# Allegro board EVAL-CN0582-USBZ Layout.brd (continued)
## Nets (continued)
UNNAMED_27_ADA45221_I223_: A14.2 R312.1 R318.2(N2)
UNNAMED_27_ADA45221_I223_OUT: A14.6 D4.3 R312.2(N2) R351.2(N2) TP59.1(N1)
UNNAMED_27_ADA45221_I227_: A5.3 C185.2(N2) R160.2(N2)
UNNAMED_27_ADG1219_I151_D: A14.3 TP57.1(N1) U32.6
UNNAMED_27_ADG1219_I151_EN: R310.2(N2) U32.1
UNNAMED_27_ADG1219_I151_SB: A5.6 C216.1 R112.1 TP32.1(N1) U32.5
UNNAMED_27_CAP_I189_N2: C243.2(N2) C244.1 R148.2(N2) R157.1 R311.1 R345.1
UNNAMED_27_CAP_I238_N2: C291.2(N2) R343.2(N2)
UNNAMED_27_CAP_I250_N2: C216.2(N2) R159.2(N2) R160.1
UNNAMED_27_CNBNC2P_I81_CNTR: D4.4 D5.2(N2) J6.1 R351.1
UNNAMED_27_DIO4PV11_I83_A1: D4.1 R121.2(N2)
UNNAMED_27_DIO4PV11_I83_K2: D4.2(K2) R228.2(N2)
UNNAMED_27_RES_I13_N2: R153.2(N2) Y4.3
UNNAMED_27_RES_I119_N2: A5.2 R99.2(N2) R112.2(N2)
UNNAMED_28_AD568XRV5_I11_VREF: C146.2(N2) R128.1 U16.15(VREF)
UNNAMED_28_AD77684_I28_AVDD1A: C163.1 C164.1 E2.2(N2) U18.4 U18.45
UNNAMED_28_AD77684_I28_AVDD2A: C165.1 C166.1 E3.2(N2) U18.53 U18.60
UNNAMED_28_AD77684_I28_DIN: R150.2(N2) U18.21
UNNAMED_28_AD77684_I28_DNC: R258.1 U18.20
UNNAMED_28_AD77684_I28_DREGCAP: C169.1 C171.1 U18.34
UNNAMED_28_AD77684_I28_IOVDD: C167.2(N2) C168.2(N2) E4.1 U18.35
UNNAMED_28_AD77684_I28_PINN: R149.2(N2) TP7.1(N1) U18.57
UNNAMED_28_AD77684_I28_REG1CAPA: C174.1 C175.1 U18.61
UNNAMED_28_AD77684_I28_REG2CAPB: C172.1 C173.1 U18.52
UNNAMED_28_AD77684_I28_SYNCOUTN: R151.2(N2) U18.38
UNNAMED_28_ADA48071_I285_: A6.4 C152.1 R139.1
UNNAMED_28_ADA48071_I285__1: A6.3 R132.2(N2)
UNNAMED_28_ADA48071_I292_: A9.4 R142.1 R143.2(N2)
UNNAMED_28_ADA48071_I307_: A15.4 C101.1 R195.2(N2)
UNNAMED_28_ADA48071_I307__1: A15.3 C99.1 R117.2(N2) R190.2(N2)
UNNAMED_28_ADA48071_I307_DISABLEN: A15.5 R319.1
UNNAMED_28_ADA48071_I307_VOUT: A15.1(VOUT) C101.2(N2) R195.1 R253.1
UNNAMED_28_CAP_I178_N1: C12.1 E16.2(N2) R6.1 Y3.4(VCC)
UNNAMED_28_CAP_I209_N1: C13.1 E17.2(N2) R77.1 Y5.4
UNNAMED_28_CAP_I254_N2: A6.1(VOUT) C152.2(N2) R138.1
UNNAMED_28_CAP_I282_N2: C154.2(N2) R131.2(N2) R135.1
UNNAMED_28_NCTESTPAD_I237_N1: R255.2(N2) R256.1 R257.1 TP18.1(N1)
UNNAMED_28_RES_I152_N2: A9.3 R135.2(N2) R254.1
UNNAMED_28_RES_I334_N1: R373.1 Y3.3
UNNAMED_28_RES_I335_N2: Q10.G R372.2(N2) R374.1
UNNAMED_28_RES_I336_N2: R77.2(N2) R374.2(N2) Y5.1
UNNAMED_28_RES_I338_N2: Q10.D R6.2(N2) Y3.1
UNNAMED_28_RES_I341_N1: R375.1 Y5.3(OUTPUT)
UNNAMED_29_ADP1708_I198_ADJ: R226.1 R227.1 U26.8
UNNAMED_29_ADP1708_I198_EN: R224.1 U26.1
UNNAMED_29_ADP1708_I198_IN: C208.2(N2) R224.2(N2) R274.1 R275.1 U26.3 U26.4
UNNAMED_29_ADP1708_I198_SENSE: R225.2(N2) U26.7(SENSE)
UNNAMED_29_CAP_I53_N1: C142.1 U1.A5
UNNAMED_29_CAP_I54_N1: C141.1 U1.A6
UNNAMED_29_CAP_I143_N1: C90.1 D6.C R231.2(N2) U1.E10
UNNAMED_29_CAP_I208_N2: C271.2(N2) U1.A4
UNNAMED_29_CAP_I209_N2: C272.2(N2) U1.A3
UNNAMED_29_DIOSCHOTTKY_I142_P: D6.A(P) P8.2 R231.1
UNNAMED_29_ICCYUSB301X_I1_CLKIN: TP1.1(N1) U1.D7
UNNAMED_29_ICCYUSB301X_I1_GPIO: R140.2(N2) U1.J6
UNNAMED_29_ICCYUSB301X_I1_GPIO_1: R133.2(N2) U1.K10
UNNAMED_29_ICCYUSB301X_I1_GPIO_2: R120.2(N2) U1.F7
UNNAMED_29_ICCYUSB301X_I1_GPIO_3: R268.2(N2) U1.G10
UNNAMED_29_ICCYUSB301X_I1_GPIO_4: R122.2(N2) U1.G9
UNNAMED_29_ICCYUSB301X_I1_GPIO_5: R124.2(N2) U1.H10
UNNAMED_29_ICCYUSB301X_I1_GPIO_6: R119.2(N2) U1.F9
UNNAMED_29_ICCYUSB301X_I1_GPIO_7: R136.2(N2) U1.J8
UNNAMED_29_ICCYUSB301X_I1_GPIO_8: R134.2(N2) U1.K9
UNNAMED_29_ICCYUSB301X_I1_GPIO_9: R137.2(N2) U1.G8
UNNAMED_29_ICCYUSB301X_I1_GPIO_10: R152.2(N2) U1.G6
UNNAMED_29_ICCYUSB301X_I1_GPIO_11: R144.2(N2) U1.K7
UNNAMED_29_ICCYUSB301X_I1_GPIO_12: R174.1 U1.D4
UNNAMED_29_ICCYUSB301X_I1_GPIO_13: R176.1 U1.C2
UNNAMED_29_ICCYUSB301X_I1_GPIO_14: R175.1 U1.C1
UNNAMED_29_ICCYUSB301X_I1_GPIO_15: R273.1 U1.D3
UNNAMED_29_ICCYUSB301X_I1_GPIO_16: R173.1 U1.D2
UNNAMED_29_ICCYUSB301X_I1_GPIO_17: R177.1 U1.D5
UNNAMED_29_ICCYUSB301X_I1_GPIO_18: R172.1 U1.D1
UNNAMED_29_ICCYUSB301X_I1_GPIO_19: R270.1 U1.C4
UNNAMED_29_ICCYUSB301X_I1_GPIO_20: R219.1 U1.E5
UNNAMED_29_ICCYUSB301X_I1_GPIO_21: R171.1 U1.E4
UNNAMED_29_ICCYUSB301X_I1_GPIO_22: R169.1 U1.H4
UNNAMED_29_ICCYUSB301X_I1_GPIO_23: R271.1 U1.H5
UNNAMED_29_ICCYUSB301X_I1_GPIO_24: R170.1 U1.L4
UNNAMED_29_ICCYUSB301X_I1_GPIO_25: R215.1 U1.F4
UNNAMED_29_ICCYUSB301X_I1_GPIO_26: R232.1 U1.F5
UNNAMED_29_ICCYUSB301X_I1_GPIO_27: R272.1 U1.F2
UNNAMED_29_ICCYUSB301X_I1_GPIO_28: R213.1 U1.H2
UNNAMED_29_ICCYUSB301X_I1_GPIO_29: R212.1 U1.J1
UNNAMED_29_ICCYUSB301X_I1_GPIO_30: R218.1 U1.F3
UNNAMED_29_ICCYUSB301X_I1_GPIO_31: R214.1 U1.H3
UNNAMED_29_ICCYUSB301X_I1_GPIO_32: R216.1 U1.G2
UNNAMED_29_ICCYUSB301X_I1_GPIO_33: R217.1 U1.G3
UNNAMED_29_ICCYUSB301X_I1_GPIO_34: R233.1 U1.E1
UNNAMED_29_ICCYUSB301X_I1_GPIO_35: R161.1 U1.J3
UNNAMED_29_ICCYUSB301X_I1_GPIO_36: R168.1 U1.G4
UNNAMED_29_ICCYUSB301X_I1_GPIO_37: R220.1 U1.K2
UNNAMED_29_ICCYUSB301X_I1_GPIO_38: R221.1 U1.J4
UNNAMED_29_ICCYUSB301X_I1_GPIO_39: R222.1 U1.K1
UNNAMED_29_ICCYUSB301X_I1_GPIO_40: R223.1 U1.J2
UNNAMED_29_ICCYUSB301X_I1_GPIO_41: R118.2(N2) U1.F10
UNNAMED_29_ICCYUSB301X_I1_GPIO_42: R130.2(N2) U1.L10
UNNAMED_29_ICCYUSB301X_I1_GPIO_43: R129.2(N2) U1.K11
UNNAMED_29_ICCYUSB301X_I1_GPIO_44: R127.2(N2) U1.J9
UNNAMED_29_ICCYUSB301X_I1_GPIO_45: R126.2(N2) U1.J10
UNNAMED_29_ICCYUSB301X_I1_GPIO_46: R125.2(N2) U1.H9
UNNAMED_29_ICCYUSB301X_I1_GPIO_47: R123.2(N2) U1.F8
UNNAMED_29_ICCYUSB301X_I1_GPIO_48: R165.2(N2) U1.K5
UNNAMED_29_ICCYUSB301X_I1_GPIO_49: R166.2(N2) U1.J5
UNNAMED_29_ICCYUSB301X_I1_GPIO_50: R164.2(N2) U1.H6
UNNAMED_29_ICCYUSB301X_I1_GPIO_51: R163.2(N2) U1.G5
UNNAMED_29_ICCYUSB301X_I1_GPIO_52: R162.2(N2) U1.H8
UNNAMED_29_ICCYUSB301X_I1_GPIO_53: R147.2(N2) U1.G7
UNNAMED_29_ICCYUSB301X_I1_GPIO_54: R146.2(N2) U1.H7
UNNAMED_29_ICCYUSB301X_I1_GPIO_55: R145.2(N2) U1.J7
UNNAMED_29_ICCYUSB301X_I1_GPIO_56: R141.2(N2) U1.K8
UNNAMED_29_ICCYUSB301X_I1_GPIO_57: R269.2(N2) U1.K6
UNNAMED_29_ICCYUSB301X_I1_I2CGPIO: R235.1 U1.D10
UNNAMED_29_ICCYUSB301X_I1_I2CGPIO_1: R234.1 U1.D9
UNNAMED_29_ICCYUSB301X_I1_O: TP3.1(N1) U1.D11
UNNAMED_29_ICCYUSB301X_I1_RUSB2: R178.2(N2) U1.C8
UNNAMED_29_ICCYUSB301X_I1_RUSB3: R167.2(N2) U1.B3
UNNAMED_30_CN10P_I90_N1: P7.1 R230.1
UNNAMED_30_DIOLED_I129_N: DS2.C R182.1
UNNAMED_30_RES_I2_N1: R183.1 Y2.3
UNNAMED_30_RES_I10_N2: R180.2(N2) Y2.1
UNNAMED_30_RES_I76_N1: R191.1 S1.1B(N4)
UNNAMED_30_RES_I130_N2: Q2.D R182.2(N2)
UNNAMED_30_RES_I131_N2: Q2.G R181.2(N2)
UNNAMED_31_74LVC1G04_I124_A: R334.1 U37.5 U38.2
UNNAMED_31_74LVC1G04_I124_Y: R335.1 R340.2(N2) U38.4(Y) U41.2
UNNAMED_31_74LVC1G04_I136_Y: R339.2(N2) U41.4(Y)
UNNAMED_31_ADG839_I121_S1: D19.2(N2) P5.2 R337.1 R338.2(N2) U37.4
UNNAMED_31_ADLTC4332_I1_LINKN: R249.2(N2) U12.5
UNNAMED_31_ADLTC4332_I1_REMOTE: R239.1 R244.1 U12.4
UNNAMED_31_ADLTC4332_I1_SPEED1: R242.1 R243.2(N2) U12.14
UNNAMED_31_ADLTC4332_I1_SPEED2: R240.1 R241.2(N2) U12.15
UNNAMED_31_ADLTC4332_I1_SSCN: R245.2(N2) R352.2(N2) U12.6
UNNAMED_31_ADLTC4332_I1_VCC: C17.1 R247.1 R248.2(N2) R249.1 U12.1
UNNAMED_31_CAP_I93_N2: C240.2(N2) D8.C R333.1 U3.4(Y)
UNNAMED_31_ICMAX7312_I57_AD0: R323.2(N2) R324.1 U40.21
UNNAMED_31_ICMAX7312_I57_I: TP60.1(N1) U40.17
UNNAMED_31_ICMAX7312_I57_I_1: TP61.1(N1) U40.18
UNNAMED_31_ICMAX7312_I57_I_2: TP65.1(N1) U40.20
UNNAMED_31_ICMAX7312_I57_I_3: TP64.1(N1) U40.19
UNNAMED_31_ICMAX14595_I66_TSN: R320.1 U39.4
UNNAMED_31_RES_I83_N1: R314.1 U33.2
UNNAMED_31_RES_I116_N1: R330.2(N2) R331.1 R332.2(N2) Y6.1
VOCM: A9.1(VOUT) C154.1 C270.1 R7.1 R142.2(N2) R264.1 R266.1 R358.1 TP24.1(N1)
VOCM_ADC: C268.1 R78.1 R253.2(N2) R265.1 R267.1 R359.1 TP25.1(N1)
VREF: C145.1 C269.1 R88.1 R128.2(N2) R131.1 R132.1 R345.2(N2) TP21.1(N1) U17.6(VOUT)
VREG: C98.2(N2) R82.2(N2) R84.2(N2) R86.2(N2) TP2.1(N1) U15.16(VREG)
XTAL_IN: C202.1 U1.C6 Y1.1
XTAL_OUT: C204.1 U1.C7(XTALOUT) Y1.3(N2)

Pads without a net: A5 1 5 8; A7 1 5 8; A8 1 5 8; A14 1 5 8; FL2 A1 A2 C1 C2; M1 A8 B8; P7 5; U1 A11; U3 1; U4 1 6; U5 1 6; U7 1 6; U8 1 6; U13 2; U17 1 3 5 7 8; U18 22 23; U22 5 7 8 13 14; U24 4; U27 5 7 8 13 14; U28 5 7 8 13 14; U29 5 7 8 13 14; U33 1; U38 1; U40 1; U41 1

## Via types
v1: diameter 0.508, hole 0.254, TOP to BOTTOM, 2180 vias
v2: diameter 0.457, hole 0.203, TOP to BOTTOM, 79 vias

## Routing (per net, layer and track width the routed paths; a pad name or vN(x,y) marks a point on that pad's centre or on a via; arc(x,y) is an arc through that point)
5V_SUPPLY: length 147
  TOP w0.203: 44.33,25.78 44.7,25.41 U1.E11 ; U39.8 73.91,42.15 74.04,42.28
  TOP w0.254: 74.04,42.28 C282.1
  TOP w0.305: 42.55,27.05 43.18,26.42 43.69,26.42 44.33,25.78 ; v1(75.3,39.43) R321.1 R322.1 ; C229.1 81.37,38.09 81.94,37.52 A12.8 ; A13.8 81.81,16.57 81.24,17.14 C230.1 v1(80.37,17.14) ; DS2.A v1(4.85,65.17) ; C192.2 C191.1 72.95,94.04 U20.7 ; A11.8 81.81,55.08 81.24,55.65 C210.1 v1(80.37,55.65) ; U19.2 73.73,84.45 73.21,84.97 ; v1(81.6,75.06) 81.68,75.14 C67.1 81.77,76.03 A10.8
  TOP w0.508: A15.6 58.62,57.01 C102.1 C105.2 57.35,55.93 57.15,56.13 v1(57.15,57.07) R319.2 ; C229.1 v1(80.53,38.09) ; v1(82.65,31.84) C306.1 C301.1 84.5,31.89 A18.6 ; 42.55,27.05 42.55,27.82 C283.1 42.16,27.95 41.8,28.31 41.8,30.09 44.01,32.31 51,32.31 51.77,31.55 60.73,31.55 61.34,30.94 61.34,29.59 v1(61.21,29.46) ; v1(49.28,72.64) C137.1 C134.1 50.43,71.75 U17.2 ; v1(70.48,84.96) 71.21,84.96 v1(71.22,84.97) C177.1 C179.2 73.26,84.97 74.05,85.76 C178.2 ; A16.6 84.38,49.44 C299.1 C304.1 v1(82.52,49.4) ; C192.2 71.24,93.99 71.12,94.11 v1(71.09,94.11) ; v1(44.32,59.25) 40.45,59.25 40.39,59.18 R8.2 R293.1 v1(38.98,57.21) ; v1(82.52,10.88) C305.1 C302.1 84.38,10.93 A19.6 ; C282.1 74.3,42.93 75.18,43.81 R324.2 v1(75.95,44.25) ; v1(82.55,70.87) 82.8,70.87 C303.1 C300.1 85.62,70.35 A17.6
  TOP w0.635: C184.1 C158.1 50.62,64.33 A9.6 ; C184.1 v1(48.78,64.25) ; C184.1 v1(49.53,65.01)
  BOTTOM w0.305: U16.3 62.38,46.73 C133.1 C132.1 ; U40.24 70.96,42.85 70.89,42.92 C233.1
  BOTTOM w0.508: E2.1 45.17,58.55 44.61,59.11 44.47,59.11 v1(44.32,59.25) ; v1(38.98,57.21) 38.79,57.21 37.84,56.26 10.92,56.26 4.85,62.33 v1(4.85,65.17) ; R308.2 v1(81.54,15.26) ; v1(82.55,70.87) 82.55,73.41 82.42,73.53 R304.2 81.99,74.73 81.66,75.06 v1(81.6,75.06) ; R305.2 v1(81.54,53.78) ; C233.1 v1(69.98,44.07) ; R309.2 v1(81.67,36.22) ; C132.1 v1(64.11,46.5)
  vias: v1(55.4,60.05) v1(61.21,28.7) v1(61.21,27.94) v1(61.21,27.18) v1(61.21,26.42) v1(61.21,25.65) v1(61.21,24.89) v1(74.02,55.85) v1(74.02,54.97) v1(74.04,17.78) v1(74.04,17.14) v1(74.15,77.24) v1(74.11,76.48) v1(74.17,37.72) v1(90.55,58.93) v1(90.55,20.19) v1(90.66,79.88) v1(91.06,41.27) v1(91.31,58.93) v1(91.44,79.88) v1(91.44,20.19) v1(91.69,41.27)
5V_USB: length 49.9
  TOP w0.508: v1(21.71,57.78) R297.1 C278.2
  L3_SIG w0.305: v1(8.76,41.02) 4.19,41.02 3.35,40.18 3.35,25.86 6.66,22.55 v1(6.76,22.55)
  L3_SIG w0.508: v1(9.53,42.54) 11.81,42.54 21.71,52.44 v1(21.71,57.78)
  BOTTOM w0.305: R101.2 v1(6.76,22.55)
  vias: v1(8.76,42.54) v1(8.76,41.78) v1(9.53,41.78) v1(9.53,41.02)
26V8_SUPPLY: length 14.1
  TOP w0.305: v1(13.97,76.58) R90.2 C311.1
  BOTTOM w0.305: v1(25.43,77.85) 25.4,77.83 23.42,77.83 23.14,78.11 15.44,78.11 13.97,76.63 v1(13.97,76.58)
26V_SUPPLY: length 40.2
  TOP w0.203: R80.2 32.64,71.64 C95.2 32.65,71 32.38,70.74 28.83,70.74 28.69,70.88 28.69,71.74 TP46.1
  TOP w0.305: U43.4 104,25.19 C295.1 ; C212.1 104.08,55.27 U34.4 ; C127.1 92.43,13.05 U29.11 ; U22.11 92.56,72.52 C107.1 ; C121.1 92.56,34.01 U28.11 ; C114.1 92.43,51.56 U27.11 ; C211.1 104.3,63.67 U25.4 ; U44.4 104.12,16.76 C296.1
  TOP w0.508: C296.1 103.41,16.05 C298.1 v1(101.39,16.05) ; C107.1 90.93,71.69 C115.2 v1(89.49,71.23) ; C211.1 103.55,63.51 C249.1 v1(101.85,62.83) ; C212.1 102.82,55.03 C250.1 v1(101.47,54.7) ; v1(89.49,32.72) C129.2 90.93,33.18 C121.1 ; C295.1 103.3,25.03 C297.1 v1(101.54,24.22) ; C127.1 90.8,12.23 C130.2 v1(89.36,11.76) ; v1(89.36,50.28) 90.12,50.28 C118.2 90.58,50.74 C114.1
  vias: v1(28.07,72.77) v1(28.96,72.87) v1(31.24,73.91) v1(31.37,73.28) v1(92.84,68.08) v1(92.96,59.95) v1(92.96,29.54) v1(93.34,21.46) v1(93.73,68.08) v1(93.73,59.95) v1(93.73,29.58) v1(93.98,21.46)
AVDD: length 8
  TOP w0.203: U1.A7 41.15,21.59 40.89,21.84
  TOP w0.305: C199.1 38.74,21.84 40.89,21.84
  TOP w0.508: E9.1 35.62,21.59 C196.1 36.04,22.01 37.56,22.01 C199.1
DGND: length 1416.7
  TOP w0.152: 82.73,48.39 82.43,48.39 v1(82.42,48.39) ; v1(102.11,64.39) 102.15,64.43 C249.2 ; E1.2 2.33,44.03 v1(1.91,44.45) ; 82.55,9.65 v1(82.52,9.65)
  TOP w0.203: M1.B12 7.2,35.29 7.2,35.29 v1(7.05,35.29) ; C144.2 48.51,29.58 48.9,29.97 v1(48.9,30.48) ; v2(47.24,15.24) 46.3,16.19 U1.G1 ; U18.7 46.6,55.05 v1(46.31,55.34) 46.1,55.14 U18.8 ; U1.L6 49.77,21.06 50.62,21.06 v2(50.72,21.16) ; v1(41.53,44.45) 41.53,44.63 41.02,45.14 U18.31 ; U18.42 46.6,43.65 v1(46.26,43.99) 46.1,43.83 U18.41 ; U18.55 v1(50.24,47.64) ; U1.B9 v2(41.88,23.6) ; U1.L1 49.52,16.79 v2(49.91,17.17) U1.L2 ; v1(50.15,49.14) U18.58 ; U18.10 45.1,55.14 v1(45.31,55.34) 45.6,55.05 U18.9 ; U18.40 45.6,43.65 45.47,43.78 v1(45.47,43.99) 45.31,43.84 45.31,43.66 45.1,43.44 U18.39 ; U1.B8 v2(41.88,22.8) ; U18.3 48.6,55.09 48.63,55.12 48.63,55.22 48.65,55.24 v1(48.65,55.79) ; U1.B7 v2(41.88,22) ; v1(12.32,32.26) 12.32,32.38 12.19,32.51 FL1.B1 FL1.B2 FL1.B3 v1(12.19,35.56) ; v1(12.57,30.48) 12.19,30.1 FL2.B3 FL2.B2 FL2.B1 12.19,27.3 v1(11.68,26.8) ; U1.A1 v2(41.08,16.37) ; U1.K4 v2(49.11,18.77) ; U18.5 v1(47.6,52.7) ; U14.2 v1(17.02,14.23) ; U1.D8 v2(43.48,22.8) ; U1.A8 v2(41.08,22.8) ; U18.51 52.66,45.64 52.81,45.49 v1(52.81,45.47) ; U1.L11 v2(49.91,25.2) ; 47.62,43.94 47.6,43.91 U18.44 v1(47.6,41.43) ; U1.E2 v2(44.28,17.17) ; U18.46 v1(48.6,41.43) ; U18.54 52.42,47.14 v1(52.82,46.74) ; v2(46.3,25.4) U1.G11 ; U1.L3 v2(49.91,17.97) ; M1.B1 7.2,29.79 7.2,29.79 v1(7.05,29.79) ; U18.33 v1(42.1,41.43) ; U1.K3 v2(49.11,17.97) ; U18.62 52.58,51.14
  TOP w0.254: C174.2 53.46,51.94 52.66,51.14 52.58,51.14 ; U39.5 v1(72.6,40) ; U11.3 v1(33.72,75.25) ; U26.PAD 27.82,15.36 U26.2
  TOP w0.305: v1(19.56,77.47) 19.37,77.66 U13.5 18.91,76.85 v1(19.05,76.71) ; 106.31,18.06 U44.2 104.48,18.06 ; U44.5 110.91,16.76 ; U44.5 110,16.35 ; U44.5 109.08,16.76 ; v1(106.68,64.26) 106.62,64.32 U25.3 104.33,64.32 ; 109.08,25.19 U43.5 ; U43.5 110.91,25.19 ; U43.5 110,24.78 ; 109.34,63.67 U25.5 ; U25.5 111.16,63.67 ; U25.5 110.25,63.26 ; U28.4 v1(96.99,36.01) ; 104.74,65 105.62,65 U25.2 106.62,64.97 106.68,65.02 ; C192.1 C191.2 73.2,94.69 U20.6 ; C48.2 88.05,19.45 v1(88.03,19.43) ; U27.4 v1(96.86,53.57) ; C210.2 v1(80.37,54.65) 80.37,54.64 ; 106.31,25.84 U43.3 104.48,25.84 ; U19.9 v1(77.73,84.45) ; 109.34,64.97 U25.7 111.16,64.97 ; 109.08,26.49 U43.7 110.91,26.49 ; U34.5 110.91,55.27 ; U34.5 109.08,55.27 ; U34.5 110,54.86 ; C68.2 88.05,57.96 v1(88.03,57.94) ; 106.31,17.41 U44.3 104.48,17.41 ; A10.4 v1(86.73,77.98) ; v1(9.41,36.96) 9.53,36.84 9.53,35.16 M1.A1 ; C230.2 v1(80.37,16.14) 80.37,16.13 ; 110.91,56.57 U34.7 109.08,56.57 ; U29.4 v1(96.86,15.06) ; M1.A12 9.41,29.2 v1(9.65,28.96) ; U22.4 v1(96.99,74.53) ; v1(88.16,40.37) 88.17,40.39 C35.2 ; 106.31,26.49 U43.2 104.48,26.49 ; C236.1 v1(92.18,93.99) ; 109.08,18.06 U44.7 110.91,18.06 ; U19.4 73.41,83.45 C180.2 ; A11.4 v1(84.75,57.03) ; U32.3 86.79,96.07 C239.2 v1(85.7,95.77) ; U30.20 v1(17.95,60.09) ; C50.2 88.05,20.45 v1(88.03,20.43) ; U30.11 v1(17.95,67.3) ; U30.1 v1(24.61,60.79) ; 106.31,55.92 U34.3 104.48,55.92 ; v1(85.01,39.46) 85.02,39.47 A12.4 ; 104.3,64.32 C211.2 ; D20.1 v1(8.43,83.79) ; R99.1 v1(93.98,93.24) C234.2 ; v1(28.07,88.77) 28.25,88.96 U15.15 ; 104.48,56.57 U34.2 106.31,56.57 ; C238.2 v1(85.7,93.86) ; U30.4 v1(24.64,62.74) ; A8.3 v1(77.98,98.88) ; A13.4 v1(84.75,18.52) ; v1(88.16,41.39) 88.17,41.4 C37.2 ; C70.2 88.05,58.96 v1(88.03,58.94) ; U12.16 v1(43.3,69.71) ; D13.1 v1(8.38,81.91) ; C229.2 v1(80.49,37.09) 80.5,37.08
  TOP w0.406: v1(44.07,74.42) 44.06,74.41 R251.2 ; D17.1 v1(8,8.89) ; R81.1 v1(34.8,71.75) ; TP36.1 12.32,3.81 v1(12.45,3.94) ; U15.1 v1(31.5,94.36) ; v1(86.64,16.89) A2.2 ; U37.3 12.85,90.18 C274.2 ; v1(86.64,55.4) A4.2 ; v1(86.76,76.36) A3.2 ; v1(86.76,37.85) A1.2
  TOP w0.457: v1(89.27,50.98) 89.8,51.51 R282.1 ; C155.1 45.67,13.98 ; C118.1 91.18,49.74 C114.2
  TOP w0.508: 116.17,30.86 J3.5 ; J3.5 117.6,29.43 ; J3.5 117.6,32.3 ; 37.76,30.86 C90.2 ; C90.2 38.31,31.45 ; C90.2 38.31,30.25 v1(37.6,29.54) ; v1(89.36,10.16) C130.1 91.4,11.23 C127.2 ; v1(44.32,58.42) R263.1 R259.1 ; C212.2 104.42,56.03 ; C212.2 103.25,56.03 ; C212.2 103.84,56.58 ; 93.36,97.78 R318.1 ; R318.1 93.98,98.35 ; R318.1 94.6,97.78 ; C82.2 v1(71.52,56.04) ; J4.2 112.39,16.42 ; J4.2 110.96,14.99 ; J4.2 113.83,14.99 ; J4.2 112.39,13.55 ; R98.1 24.88,90.3 ; R98.1 v1(23.38,90.3) ; R98.1 24.26,89.73 ; 100.85,49.39 R50.1 ; R50.1 100.22,49.96 ; R50.1 101.47,49.96 ; R46.1 v1(103.87,52.81) ; R46.1 103.24,51.96 ; R46.1 104.49,51.96 ; Q9.S 99.52,6.54 ; Q9.S 97.61,6.54 ; Q9.S 98.57,7.23 ; Q9.S 98.57,5.84 ; R353.1 v1(35.92,66.8) ; 71.85,76.99 C69.2 72.4,77.58 ; 72.9,96.24 C213.2 73.48,96.78 ; C180.2 C181.1 v1(71.24,83.07) ; P7.3 22.99,6.35 v1(22.48,5.84) ; C204.2 v1(35.93,30.98) ; C204.2 35.18,31.5 ; C204.2 34.49,30.98 34.49,30.95 34.08,30.53 34.04,30.53 Y1.2 ; R369.1 112.52,56.54 ; R369.1 113.09,55.92 ; R369.1 112.52,55.3 ; D11.1 v1(109.37,9.6) ; D11.1 110.45,8.42 ; D11.1 108.29,8.42 ; D11.1 109.37,7.47 ; 70.23,70.64 C85.1 69.51,69.89 ; C49.2 v1(70.87,38.48) ; 33.41,49.99 C13.2 32.86,49.4 ; 76.2,42.54 C282.2 ; R110.2 v1(51.21,95.38) ; C157.1 v1(46.72,59.8) ; R105.2 v1(51.31,93.22) ; 104.86,48.42 P2.1 ; P2.1 106.05,47.24 ; P2.1 106.05,49.6 ; P2.1 107.23,48.42 ; 52.83,93.22 TP37.1 ; TP37.1 52.83,94.74 ; TP37.1 52.07,93.98 ; TP37.1 53.59,93.98 ; 86.14,66.38 C307.2 86.69,67.17 86.74,67.22 A17.2 ; v1(21.77,75.06) 21.89,75.18 C106.1 ; v1(89.49,69.63) C115.1 91.53,70.69 C107.2 ; 69.38,55.26 C88.1 70.1,54.51 ; 82.73,69.35 C303.2 83.31,68.8 ; v1(32,22.84) 32,22.86 32.04,22.89 Y2.2 ; 3.23,62.94 DS1.C ; DS1.C v1(2.41,63.5) ; DS1.C 3.23,64.06 ; C116.1 38.34,97.88 ; C116.1 37.59,97.15 ; C116.1 36.84,97.88 ; 71.88,96.24 C215.1 71.3,96.78 ; P11.10 45.97,79.54 ; P11.10 47.16,78.36 ; P11.10 45.97,77.18 ; P11.10 44.79,78.36 ; 10.38,14.87 C94.2 ; C94.2 10.38,16.37 ; C94.2 v1(9.4,15.62) ; C26.2 v1(92.84,18.82) ; C20.1 54.36,14.48 v1(56.01,14.48) ; C225.2 30.52,57.19 U31.2 ; C225.2 31.06,56.97 ; C225.2 v1(29.41,56.97) ; C225.2 30.31,56.24 ; 28.81,49.66 Q10.S ; Q10.S 27.86,50.36 ; Q10.S 28.81,51.06 ; Q10.S 29.77,50.36 ; v1(82.58,92.32) C15.1 C14.2 ; v1(70.36,49.67) 70.34,49.69 C87.1 ; 73.48,88.91 C182.2 72.9,88.36 ; D7.1 v1(109.49,69.07) ; D7.1 108.41,67.89 ; D7.1 110.57,67.89 ; D7.1 109.49,66.93 ; 63.3,82.81 C267.1 63.88,82.27 ; C224.1 26.8,69.88 ; C224.1 25.2,68.83 ; C224.1 28.4,68.83 ; 71.3,88.91 C183.1 71.88,88.36 ; C192.1 v1(71.11,94.99) ; C92.1 v1(32.51,80.52) ; 70.23,32.13 C53.1 69.51,31.38 ; J1.2 113.96,74.45 ; J1.2 112.52,75.89 ; J1.2 112.52,73.02 ; J1.2 111.09,74.45 ; C177.2 72.01,86.52 ; C177.2 C179.1 73.03,86.61 ; C177.2 71.42,85.97 ; 86.74,11.79 A19.5 86.74,10.07 ; 57.02,48.26 56.51,47.74 R256.2 56.51,46.53 57.48,45.56 57.48,45.3 v1(57.57,45.21) ; v1(21.29,79.76) 20.74,79.76 C97.2 20.74,78.99 v1(21.29,78.99) ; 85.63,57.49 A11.4 86.42,57.03 ; 44.63,73.53 R251.2 44.06,72.91 ; R296.1 v1(14.99,25.4) 14.74,25.4 14.11,24.78 R114.2 ; 100.07,76.16 R362.2 100.64,75.54 ; C22.2 50.56,29.2 50.72,29.37 50.72,30.13 50.58,30.28 50.58,30.29 v1(50.4,30.46) ; C289.2 C290.1 v1(15.74,90.54) ; C145.2 v1(59.56,68.73) ; 82.26,85.15 C243.1 ; C243.1 84.37,85.15 ; C243.1 83.31,84.25 ; 105.75,99.06 J6.2 ; J6.2 106.81,98.01 ; J6.2 107.86,99.06 ; J6.2 106.81,100.11 ; R258.2 v1(36.32,50.93) ; 18.21,55.56 Q3.S ; Q3.S 19.16,56.26 ; Q3.S v1(20.26,55.56) ; 32.98,27.85 32.62,28.21 Y1.4 v1(31.74,28.81) ; A16.2 86.74,46.14 86.69,46.09 C308.2 86.14,45.3 ; C283.2 v1(42.67,29.85) 42.68,29.85 42.87,29.85 42.96,29.76 C18.1 ; 84.91,48.39 C299.2 84.33,47.85 ; D10.1 110.57,29.37 ; D10.1 109.49,28.42 ; D10.1 108.41,29.37 ; D10.1 v1(109.49,30.56) ; 83.31,47.85 C304.2 82.73,48.39 ; v1(70.36,11.16) 70.34,11.18 C55.1 ; C198.2 38.39,15.12 v1(37.59,14.33) ; 66.46,81.22 Y4.2 ; Y4.2 66.46,83.12 ; Y4.2 67.32,82.17 ; Y4.2 65.61,82.17 ; J4.4 113.83,9.91 ; J4.4 112.39,11.34 ; J4.4 112.39,8.47 ; J4.4 110.96,9.91 ; C185.1 v1(91.69,87.76) ; P14.3 2.54,73.62 ; P14.3 2.54,71.13 ; P14.3 3.79,72.38 ; P14.3 1.29,72.38 ; 70.23,75.44 C86.1 69.51,76.19 ; R286.1 89.49,12.94 89.49,12.7 89.28,12.49 89.28,12.48 v1(89.27,12.47) ; 28.83,77.14 C91.2 27.77,78.04 ; J2.3 117.48,54.93 ; J2.3 117.48,52.06 ; J2.3 116.04,53.5 ; TP38.1 104.52,4.7 ; TP38.1 105.28,3.94 ; TP38.1 v1(103.5,3.94) ; TP38.1 104.52,3.17 ; R190.1 64.5,59.24 C268.2 v1(65.59,59.1) ; R155.1 v1(82.43,88.65) ; v1(16.34,23.41) C257.1 C258.1 16.64,26.21 C255.2 ; C174.2 v1(53.59,52.68) ; C186.2 v1(94.73,88.65) ; 10.54,3.81 TP36.1 ; TP36.1 11.3,4.57 ; TP36.1 11.3,3.05 ; 82.73,9.88 C305.2 83.31,9.34 ; 64.9,82.27 C176.2 65.48,82.81 ; C100.1 v1(16.52,80) ; v1(20.7,100.97) 21.34,100.33 R276.1 ; v1(37.34,11.68) 37.34,11.68 37.59,11.68 38.1,12.19 R185.1 ; 103.53,97.22 D5.1 ; D5.1 104.75,97.22 ; D5.1 104.14,97.68 ; C137.2 v1(48.38,70.75) ; C137.2 C134.2 ; C137.2 v1(49.28,69.85) ; C56.1 70.29,16 v1(70.31,15.99) ; P1.1 106.17,70.55 ; P1.1 106.17,68.19 ; P1.1 104.99,69.37 ; P1.1 107.35,69.37 ; 71.85,75.98 C207.2 72.4,75.39 ; C250.2 102.49,57.02 ; C250.2 101.74,56.3 ; C250.2 103.24,56.3 ; 36.7,5.68 36.7,6.86 ; 36.7,6.86 37.88,6.86 ; 36.7,6.86 36.7,8.04 ; 31.46,76.33 U11.PAD 33.57,76.33 ; C148.1 47.51,30.74 47.62,30.86 v1(47.62,31.12) ; v1(54.61,44.01) 54.61,44.14 54.61,44.15 C173.2 ; 100.31,70.87 R49.1 ; R49.1 100.93,70.3 ; R49.1 101.55,70.87 ; 9.65,97.39 Y6.2 ; Y6.2 v1(8.16,98.65) ; Y6.2 9.65,99.9 ; Y6.2 v1(11.21,98.65) ; C54.2 69.51,37.77 ; C54.2 69.51,36.27 ; C54.2 70.3,37.02 v1(70.48,36.83) ; R15.1 101.55,32.36 ; R15.1 100.31,32.36 ; R15.1 100.93,31.79 ; 86.14,6.79 C309.2 86.69,7.57 86.74,7.62 A19.2 ; P10.5 36.7,5.5 ; P10.5 37.88,4.32 ; P10.5 36.7,3.14 ; 1.42,14.35 S2.1 ; S2.1 2.54,15.47 ; S2.1 3.66,14.35 ; S2.1 2.54,13.23 ; 33.14,31.25 R349.2 ; R349.2 33.71,31.88 ; R349.2 33.14,32.5 ; 84.91,69.35 C300.2 84.33,68.8 ; C36.2 v1(71.5,16.51) ; C136.2 47.48,12.16 v1(47.95,11.68) ; C19.2 v1(36.53,26.92) ; C285.2 9.6,76.16 C286.1 v1(9.6,76.93) ; 85.75,39.93 A12.4 86.54,39.47 ; P4.1 107.23,9.91 ; P4.1 106.05,11.09 ; P4.1 106.05,8.72 ; P4.1 104.86,9.91 ; C294.2 30.94,34.17 ; C294.2 29.77,34.17 ; C294.2 30.35,33.62 ; 96.9,6.17 R342.1 ; R342.1 97.52,6.74 ; R342.1 96.28,6.74 ; v1(81.66,85.87) C244.2 R148.1 v1(80.52,85.87) ; 16.43,93.48 C288.1 ; C288.1 17.02,92.93 ; C288.1 C273.2 v1(19.06,93.48) ; R371.1 113.09,17.41 ; R371.1 112.52,16.79 ; R371.1 112.52,18.03 ; D9.1 v1(109.37,48.11) ; D9.1 110.45,46.93 ; D9.1 109.37,45.98 ; D9.1 108.29,46.93 ; A1.5 v1(91.57,37.85) ; C113.1 v1(25.91,84.96) ; S1.2B 56.96,7.5 ; S1.2B 53.85,7.5 v1(53.59,7.24) ; S1.2B v1(55.49,6.48) ; S1.2B 55.49,8.31 ; C64.2 v1(100.6,56.93) ; R91.1 v1(13.97,75.44) ; 111.09,35.94 J3.2 ; J3.2 113.96,35.94 ; J3.2 112.52,37.38 ; J3.2 112.52,34.51 ; C80.2 v1(71.5,55.02) ; 90.3,48.13 C118.1 89.55,48.86 ; 83.44,30.29 C306.2 82.85,30.84 ; 100.39,37.08 R366.2 99.81,37.71 ; C160.2 v1(52.76,61.06) ; C199.2 v1(37.59,23.75) ; C199.2 38.02,22.98 ; C199.2 39.19,22.98 ; C199.2 38.61,23.53 ; 112.39,46.98 J2.4 ; J2.4 112.39,49.85 ; J2.4 113.83,48.42 ; J2.4 110.96,48.42 ; C79.2 v1(88.16,78.9) ; 116.04,14.99 J4.3 ; J4.3 117.48,13.55 ; J4.3 117.48,16.42 ; C105.1 v1(60.38,55.93) ; P3.1 106.17,32.04 ; P3.1 104.99,30.86 ; P3.1 107.35,30.86 ; P3.1 106.17,29.68 ; D19.1 v1(7.65,89.57) ; P11.9 47.16,75.82 ; P11.9 45.97,74.64 ; P11.9 45.97,77 ; Q4.S 18.99,52.33 R348.1 16.68,52.33 C260.1 v1(15.56,52.16) ; 86.74,50.31 A16.5 86.74,48.58 ; 117.6,73.02 J1.3 ; J1.3 117.6,75.89 ; J1.3 116.17,74.45 ; 15.23,59.55 R346.1 15.8,58.93 ; 6.32,68.07 Q2.S ; Q2.S v1(7.68,68.77) ; Q2.S 5.37,68.77 ; Q2.S 6.32,69.47 ; C96.2 28.83,76.78 ; C96.2 29.88,75.88 ; C96.2 27.77,75.88 ; v1(10.54,81.79) C246.1 C245.2 ; R108.1 v1(13.59,10.29) ; v1(89.49,31.12) C129.1 91.53,32.18 C121.2 ; U17.4 53.8,69.22 ; U17.4 v1(50.9,69.22) ; U17.4 52.45,68.66 ; 86.87,32.75 A18.5 86.87,31.02 ; C175.2 v1(54.61,52.68) ; P11.4 38.35,79.54 ; P11.4 39.54,78.36 ; P11.4 37.17,78.36 ; P11.4 38.35,77.18 ; 100.51,54.61 R363.2 99.94,55.23 ; C159.2 v1(52.32,60.05) ; R16.1 101.42,11.4 ; R16.1 100.18,11.4 ; R16.1 100.8,10.83 ; 87.07,93.86 C238.2 86.49,93.31 ; U38.3 3.28,83.51 ; U38.3 v1(2.26,82.65) ; U38.3 1.24,83.51 ; R368.1 113.47,64.32 ; R368.1 112.9,63.7 ; R368.1 112.9,64.94 ; v1(67.44,42.29) C281.2 ; C278.1 24.68,59.8 ; C278.1 v1(25.91,59.05) ; C278.1 24.68,58.31 ; 37.17,75.82 P11.3 ; P11.3 38.35,74.64 ; P11.3 39.54,75.82 ; P11.3 38.35,77 ; 111.09,30.86 J3.4 ; J3.4 112.52,32.3 ; J3.4 112.52,29.43 ; J3.4 113.96,30.86 ; J1.4 113.96,69.37 ; J1.4 112.52,70.81 ; J1.4 112.52,67.94 ; J1.4 111.09,69.37 ; P12.2 5.31,58.8 ; P12.2 2.82,58.8 ; P12.2 4.06,60.05 ; 85.04,30.84 C301.2 84.45,30.29 ; C57.2 v1(92.96,65.45) ; 27.09,41.21 Y3.2 ; Y3.2 27.95,42.16 ; Y3.2 26.24,42.16 ; Y3.2 27.09,43.12 ; C147.2 v1(53.45,23.74) ; C293.N 23.65,37.91 ; C293.N 25.2,36.45 ; C293.N 23.65,34.99 ; C293.N 22.1,36.45 ; C171.2 v1(40.89,39.5) ; 85.63,18.98 A13.4 86.42,18.52 ; v1(42.04,58.42) R261.1 R260.1 ; C109.2 23.75,100.83 C111.2 v1(23.76,101.61) ; v1(35.81,57.15) 36.35,56.61 C227.2 ; C25.2 v1(92.96,26.94) ; R254.2 v1(56.89,67.3) ; R254.2 55.26,67.3 ; R254.2 55.88,67.87 ; v1(36.07,13.59) 36.07,14.1 36.58,14.6 C195.1 ; R260.1 40.89,58.22 ; R260.1 40.27,57.65 ; C31.2 v1(100.73,26.67) ; R12.1 v1(103.87,14.3) ; R12.1 103.24,13.45 ; R12.1 104.49,13.45 ; 33.33,33.4 U42.3 32.91,32.68 ; 86.74,69.66 A17.5 86.74,71.39 ; v1(29.08,63.63) 28.49,63.63 C217.1 28.49,64.39 v1(29.08,64.39) ; 70.29,54.51 v1(70.31,54.5) ; A2.5 v1(91.31,16.89) ; 116.17,69.37 J1.5 ; J1.5 117.6,67.94 ; J1.5 117.6,70.81 ; 117.6,34.51 J3.3 ; J3.3 117.6,37.38 ; J3.3 116.17,35.94 ; 99.81,16.62 R367.2 100.39,16 ; 103.37,72.91 R45.1 ; R45.1 104.62,72.91 ; R45.1 v1(103.99,73.76) ; 9.84,86.89 U33.3 ; U33.3 v1(10.35,87.95) ; U33.3 10.35,85.88 ; C203.2 v1(27.69,23.26) ; 84.91,9.88 C302.2 84.33,9.34 ; R338.1 v1(11.68,92.58) ; v1(89.4,71.94) 89.41,71.94 89.41,71.96 89.62,72.17 89.62,72.41 R281.1 ; 2.54,87.89 P5.3 ; P5.3 3.79,89.14 ; P5.3 1.29,89.14 ; P5.3 2.54,90.38 ; v1(35.81,69.98) 35.82,69.97 C16.1 ; 21.6,84.8 C112.2 ; C112.2 23.1,84.8 ; C112.2 v1(22.35,83.87) ; R370.1 112.52,26.46 ; R370.1 112.52,25.21 ; R370.1 113.09,25.84 ; 35.43,71.25 C17.2 36.16,72 ; v1(89.27,50.98) 89.27,51 89.28,51 ; v1(27.05,101.09) 26.34,101.09 25.91,100.66 R96.1 ; A4.5 v1(91.4,55.4) ; J2.2 112.39,54.93 ; J2.2 112.39,52.06 ; J2.2 110.96,53.5 ; J2.2 113.83,53.5 ; J4.5 117.48,11.34 ; J4.5 116.04,9.91 ; J4.5 117.48,8.47 ; 50.42,8.04 P9.1 50.42,5.68 ; v1(18.16,76.71) v1(19.05,76.71) v1(21.72,76.71) C108.1 ; U3.3 10.98,71.09 ; U3.3 v1(10.47,69.78) ; U3.3 10.47,72.11 ; v1(11.2,9.53) C206.2 ; R243.1 v1(47.37,69.6) ; R227.2 v1(32.56,16.18) ; C218.1 v1(14.47,61.59) ; C126.2 v1(48.86,88.07) ; C110.2 v1(23.62,84.81) ; C32.2 100.33,18.41 v1(100.71,18.8) ; v1(9.47,53.24) D18.A v1(8.05,51.82) ; U2.4 v1(61.38,39.12) ; TP13.1 96.01,101.22 ; TP13.1 95.25,101.98 ; TP13.1 v1(94.23,101.22) ; TP13.1 95.25,100.46 ; Y5.2 33.32,45.6 ; Y5.2 33.32,44 ; Y5.2 32.57,44.8 ; v1(30.48,62.36) 30.23,62.36 R290.1 ; 85.75,78.44 A10.4 84.97,77.98 ; C276.1 v1(7.37,87) ; 117.48,46.98 J2.5 ; J2.5 116.04,48.42 ; J2.5 117.48,49.85 ; R198.1 v1(64.9,37.85) ; v1(35.18,27.2) C202.2 34.39,27.95 ; R332.1 v1(19.06,97.92) ; R239.2 v1(35.54,64.64) ; C269.2 v1(60.71,68.73) ; C196.2 v1(34.61,23.81) ; C99.2 61.02,59.24 A15.2 v1(60.1,59.23) ; C169.2 v1(40.89,40.51) ; C81.2 v1(88.16,79.91) ; v1(50.04,98.93) 51.02,98.93 C128.2 v1(51.31,97.71) ; 38.87,37.59 38.87,37.73 ; v1(56.01,18.6) 54.37,18.6 C24.2 ; v1(76.73,44.83) 76.23,45.34 R323.1 ; C205.2 v1(52.97,34.05) ; A6.2 v1(53.34,57.66) ; v1(46.41,14.34) 46.27,14.2 45.89,14.2 45.67,13.98 ; C274.2 v1(13.84,90.42) ; C275.2 v1(6.35,87) ; C14.2 80.77,92.87 ; C14.2 80.19,92.32 ; U23.2 45.22,99.06 C125.2 45.21,98.55 44.97,98.31 v1(44.97,98.31) ; C189.2 C214.1 v1(82.54,98.56) ; v1(55.99,17.58) C138.1 ; 26.38,36.81 v1(25.38,36.81) ; v1(89.4,33.43) 89.41,33.43 89.41,33.45 89.62,33.65 89.62,33.9 R285.1 ; C102.2 v1(60.4,56.95) ; C58.2 v1(92.84,57.2) ; R278.2 v1(35.56,54.36) ; C67.2 v1(79.93,75.95) ; C151.2 C155.1 ; C47.2 v1(70.87,37.46) ; R11.1 v1(103.99,35.25) ; R11.1 104.62,34.4 ; R11.1 103.37,34.4 ; C103.2 v1(27.48,85.72) ; A3.5 v1(91.57,76.36) ; C172.2 v1(53.59,43.96) ; 7.77,81.12 D13.1 8.99,81.12 ; U41.3 v1(16.95,83.25) ; R167.1 36.78,17.86 v1(36.7,17.78) ; C38.2 v1(71.52,17.53) ; C104.1 v1(27.05,87.12) ; C21.1 v1(36.83,25.91) ; R262.1 v1(43.18,58.42) ; C240.1 v1(10.62,76.81) ; R150.1 v1(36.32,49.78) ; C188.1 v1(92.96,87.88) ; 86.27,27.74 C310.2 86.82,28.53 86.87,28.58 A18.2 ; Q1.S v1(16.06,55.56) ; C63.2 v1(100.73,65.18) ; R241.1 v1(47.37,71.88)
  TOP w0.635: R143.1 v1(49.54,68.32) ; A9.2 55.12,65.28 55.25,65.14 C270.2 56.14,65.41 v1(56.9,65.41) ; C158.2 v1(50.55,62.5) ; C184.2 v1(48.78,63.25)
  L2_GND w0.508: P11.10 47.16,78.36 ; P11.10 44.79,78.36 ; P11.10 45.97,77.18 ; P11.10 45.97,79.54 ; P11.3 38.35,77 ; P11.3 39.54,75.82 ; P11.3 37.17,75.82 ; P11.3 38.35,74.64 ; 36.7,5.68 36.7,6.86 ; 36.7,6.86 36.7,8.04 ; 36.7,6.86 37.88,6.86 ; 36.7,6.86 35.52,6.86 ; 110.96,9.91 J4.4 ; J4.4 113.83,9.91 ; J4.4 112.39,8.47 ; J4.4 112.39,11.34 ; 36.7,3.14 P10.5 ; P10.5 35.52,4.32 ; P10.5 37.88,4.32 ; P10.5 36.7,5.5 ; 49.24,6.86 P9.1 ; P9.1 51.6,6.86 ; P9.1 50.42,5.68 ; P9.1 50.42,8.04 ; 1.29,89.14 P5.3 ; P5.3 3.79,89.14 ; P5.3 2.54,90.38 ; P5.3 2.54,87.89 ; J1.2 112.52,75.89 ; J1.2 113.96,74.45 ; J1.2 111.09,74.45 ; J1.2 112.52,73.02 ; J3.2 113.96,35.94 ; J3.2 111.09,35.94 ; J3.2 112.52,34.51 ; J3.2 112.52,37.38 ; 104.99,69.37 P1.1 ; P1.1 107.35,69.37 ; P1.1 106.17,70.55 ; P1.1 106.17,68.19 ; 116.04,9.91 J4.5 ; J4.5 117.48,11.34 ; J4.5 117.48,8.47 ; 45.97,74.64 P11.9 ; P11.9 44.79,75.82 ; P11.9 45.97,77 ; P11.9 47.16,75.82 ; 104.99,30.86 P3.1 ; P3.1 107.35,30.86 ; P3.1 106.17,32.04 ; P3.1 106.17,29.68 ; 116.04,53.5 J2.3 ; J2.3 117.48,54.93 ; J2.3 117.48,52.06 ; J6.2 106.81,100.11 ; J6.2 106.81,98.01 ; J6.2 105.75,99.06 ; J6.2 107.86,99.06 ; 117.6,73.02 J1.3 ; J1.3 117.6,75.89 ; J1.3 116.17,74.45 ; J1.5 117.6,70.81 ; J1.5 117.6,67.94 ; J1.5 116.17,69.37 ; P14.3 2.54,73.62 ; P14.3 3.79,72.38 ; P14.3 2.54,71.13 ; P14.3 1.29,72.38 ; 110.96,14.99 J4.2 ; J4.2 112.39,13.55 ; J4.2 112.39,16.42 ; J4.2 113.83,14.99 ; 116.17,35.94 J3.3 ; J3.3 117.6,34.51 ; J3.3 117.6,37.38 ; 2.82,58.8 P12.2 ; P12.2 4.06,57.56 ; P12.2 5.31,58.8 ; P12.2 4.06,60.05 ; P2.1 107.23,48.42 ; P2.1 106.05,47.24 ; P2.1 104.86,48.42 ; P2.1 106.05,49.6 ; P11.4 38.35,79.54 ; P11.4 38.35,77.18 ; P11.4 39.54,78.36 ; P11.4 37.17,78.36 ; 104.86,9.91 P4.1 ; P4.1 107.23,9.91 ; P4.1 106.05,8.72 ; P4.1 106.05,11.09 ; 117.48,13.55 J4.3 ; J4.3 117.48,16.42 ; J4.3 116.04,14.99 ; S2.1 2.54,15.47 ; S2.1 3.66,14.35 ; S2.1 2.54,13.23 ; S2.1 1.42,14.35 ; J1.4 113.96,69.37 ; J1.4 112.52,67.94 ; J1.4 111.09,69.37 ; J1.4 112.52,70.81 ; J3.4 113.96,30.86 ; J3.4 112.52,29.43 ; J3.4 111.09,30.86 ; J3.4 112.52,32.3 ; 116.17,30.86 J3.5 ; J3.5 117.6,29.43 ; J3.5 117.6,32.3 ; 110.96,48.42 J2.4 ; J2.4 112.39,49.85 ; J2.4 112.39,46.98 ; J2.4 113.83,48.42 ; 110.96,53.5 J2.2 ; J2.2 112.39,54.93 ; J2.2 113.83,53.5 ; J2.2 112.39,52.06 ; 117.48,46.98 J2.5 ; J2.5 117.48,49.85 ; J2.5 116.04,48.42
  L3_SIG w0.508: 2.54,87.89 P5.3 ; P5.3 1.29,89.14 ; P5.3 3.79,89.14 ; P5.3 2.54,90.38 ; J4.5 117.48,11.34 ; J4.5 116.04,9.91 ; J4.5 117.48,8.47 ; P3.1 107.35,30.86 ; P3.1 106.17,29.68 ; P3.1 106.17,32.04 ; P3.1 104.99,30.86 ; 112.52,29.43 J3.4 ; J3.4 113.96,30.86 ; J3.4 111.09,30.86 ; J3.4 112.52,32.3 ; P11.3 39.54,75.82 ; P11.3 38.35,74.64 ; P11.3 38.35,77 ; P11.3 37.17,75.82 ; 116.04,14.99 J4.3 ; J4.3 117.48,16.42 ; J4.3 117.48,13.55 ; 110.96,48.42 J2.4 ; J2.4 112.39,49.85 ; J2.4 113.83,48.42 ; J2.4 112.39,46.98 ; J2.2 113.83,53.5 ; J2.2 112.39,52.06 ; J2.2 112.39,54.93 ; J2.2 110.96,53.5 ; 116.17,74.45 J1.3 ; J1.3 117.6,75.89 ; J1.3 117.6,73.02 ; 111.09,69.37 J1.4 ; J1.4 112.52,70.81 ; J1.4 113.96,69.37 ; J1.4 112.52,67.94 ; 106.05,8.72 P4.1 ; P4.1 104.86,9.91 ; P4.1 106.05,11.09 ; P4.1 107.23,9.91 ; J6.2 106.81,100.11 ; J6.2 105.75,99.06 ; J6.2 106.81,98.01 ; J6.2 107.86,99.06 ; J2.3 117.48,54.93 ; J2.3 116.04,53.5 ; J2.3 117.48,52.06 ; P12.2 5.31,58.8 ; P12.2 2.82,58.8 ; P12.2 4.06,57.56 ; P12.2 4.06,60.05 ; P14.3 2.54,73.62 ; P14.3 3.79,72.38 ; P14.3 2.54,71.13 ; P14.3 1.29,72.38 ; 112.39,8.47 J4.4 ; J4.4 110.96,9.91 ; J4.4 112.39,11.34 ; J4.4 113.83,9.91 ; S2.1 2.54,15.47 ; S2.1 2.54,13.23 ; S2.1 1.42,14.35 ; S2.1 3.66,14.35 ; 117.6,29.43 J3.5 ; J3.5 116.17,30.86 ; J3.5 117.6,32.3 ; 36.7,6.86 36.7,8.04 ; 36.7,6.86 36.7,5.68 ; 36.7,6.86 37.88,6.86 ; 36.7,6.86 35.52,6.86 ; 45.97,77.18 P11.10 ; P11.10 45.97,79.54 ; P11.10 44.79,78.36 ; P11.10 47.16,78.36 ; P1.1 107.35,69.37 ; P1.1 106.17,70.55 ; P1.1 106.17,68.19 ; P1.1 104.99,69.37 ; 111.09,74.45 J1.2 ; J1.2 112.52,73.02 ; J1.2 113.96,74.45 ; J1.2 112.52,75.89 ; P11.4 39.54,78.36 ; P11.4 38.35,79.54 ; P11.4 38.35,77.18 ; P11.4 37.17,78.36 ; 116.17,35.94 J3.3 ; J3.3 117.6,34.51 ; J3.3 117.6,37.38 ; 50.42,5.68 P9.1 ; P9.1 51.6,6.86 ; P9.1 49.24,6.86 ; 36.7,3.14 P10.5 ; P10.5 35.52,4.32 ; P10.5 36.7,5.5 ; P10.5 37.88,4.32 ; 110.96,14.99 J4.2 ; J4.2 112.39,16.42 ; J4.2 113.83,14.99 ; J4.2 112.39,13.55 ; 116.04,48.42 J2.5 ; J2.5 117.48,49.85 ; J2.5 117.48,46.98 ; 44.79,75.82 P11.9 ; P11.9 47.16,75.82 ; P11.9 45.97,77 ; P11.9 45.97,74.64 ; 106.05,47.24 P2.1 ; P2.1 104.86,48.42 ; P2.1 107.23,48.42 ; P2.1 106.05,49.6 ; J3.2 113.96,35.94 ; J3.2 112.52,34.51 ; J3.2 112.52,37.38 ; J3.2 111.09,35.94 ; J1.5 117.6,70.81 ; J1.5 117.6,67.94 ; J1.5 116.17,69.37
  L5_GND w0.508: 35.52,6.86 36.7,6.86 ; 36.7,6.86 37.88,6.86 ; 36.7,6.86 36.7,5.68 ; 36.7,6.86 36.7,8.04 ; P11.3 39.54,75.82 ; P11.3 37.17,75.82 ; P11.3 38.35,77 ; P11.3 38.35,74.64 ; P11.4 39.54,78.36 ; P11.4 38.35,77.18 ; P11.4 38.35,79.54 ; P11.4 37.17,78.36 ; J1.3 117.6,75.89 ; J1.3 116.17,74.45 ; J1.3 117.6,73.02 ; 106.17,29.68 P3.1 ; P3.1 104.99,30.86 ; P3.1 107.35,30.86 ; P3.1 106.17,32.04 ; 112.52,73.02 J1.2 ; J1.2 111.09,74.45 ; J1.2 112.52,75.89 ; J1.2 113.96,74.45 ; 110.96,53.5 J2.2 ; J2.2 112.39,52.06 ; J2.2 113.83,53.5 ; J2.2 112.39,54.93 ; P14.3 3.79,72.38 ; P14.3 1.29,72.38 ; P14.3 2.54,73.62 ; P14.3 2.54,71.13 ; J3.2 113.96,35.94 ; J3.2 112.52,37.38 ; J3.2 111.09,35.94 ; J3.2 112.52,34.51 ; 105.75,99.06 J6.2 ; J6.2 107.86,99.06 ; J6.2 106.81,100.11 ; J6.2 106.81,98.01 ; 116.04,9.91 J4.5 ; J4.5 117.48,8.47 ; J4.5 117.48,11.34 ; J3.4 113.96,30.86 ; J3.4 112.52,29.43 ; J3.4 112.52,32.3 ; J3.4 111.09,30.86 ; J4.4 112.39,11.34 ; J4.4 110.96,9.91 ; J4.4 112.39,8.47 ; J4.4 113.83,9.91 ; P9.1 50.42,8.04 ; P9.1 50.42,5.68 ; P9.1 51.6,6.86 ; P9.1 49.24,6.86 ; 106.05,47.24 P2.1 ; P2.1 106.05,49.6 ; P2.1 104.86,48.42 ; P2.1 107.23,48.42 ; P10.5 37.88,4.32 ; P10.5 36.7,5.5 ; P10.5 36.7,3.14 ; P10.5 35.52,4.32 ; 2.82,58.8 P12.2 ; P12.2 5.31,58.8 ; P12.2 4.06,60.05 ; P12.2 4.06,57.56 ; J2.5 117.48,49.85 ; J2.5 116.04,48.42 ; J2.5 117.48,46.98 ; 110.96,48.42 J2.4 ; J2.4 112.39,46.98 ; J2.4 113.83,48.42 ; J2.4 112.39,49.85 ; P1.1 106.17,70.55 ; P1.1 107.35,69.37 ; P1.1 106.17,68.19 ; P1.1 104.99,69.37 ; J1.4 113.96,69.37 ; J1.4 111.09,69.37 ; J1.4 112.52,70.81 ; J1.4 112.52,67.94 ; 45.97,77.18 P11.10 ; P11.10 45.97,79.54 ; P11.10 44.79,78.36 ; P11.10 47.16,78.36 ; P4.1 107.23,9.91 ; P4.1 106.05,8.72 ; P4.1 106.05,11.09 ; P4.1 104.86,9.91 ; J3.3 117.6,37.38 ; J3.3 117.6,34.51 ; J3.3 116.17,35.94 ; P11.9 47.16,75.82 ; P11.9 45.97,77 ; P11.9 44.79,75.82 ; P11.9 45.97,74.64 ; 117.6,29.43 J3.5 ; J3.5 116.17,30.86 ; J3.5 117.6,32.3 ; 117.48,52.06 J2.3 ; J2.3 116.04,53.5 ; J2.3 117.48,54.93 ; J4.2 113.83,14.99 ; J4.2 110.96,14.99 ; J4.2 112.39,13.55 ; J4.2 112.39,16.42 ; S2.1 3.66,14.35 ; S2.1 1.42,14.35 ; S2.1 2.54,13.23 ; S2.1 2.54,15.47 ; 1.29,89.14 P5.3 ; P5.3 2.54,90.38 ; P5.3 3.79,89.14 ; P5.3 2.54,87.89 ; 117.6,67.94 J1.5 ; J1.5 116.17,69.37 ; J1.5 117.6,70.81 ; 116.04,14.99 J4.3 ; J4.3 117.48,16.42 ; J4.3 117.48,13.55
  BOTTOM w0.152: U35.11 20.58,28.27 20.69,28.38 20.76,28.38 v1(20.83,28.45) ; v1(43.43,27.03) 43.43,27.02 43.43,26.29 43.56,26.16 C135.2
  BOTTOM w0.203: U36.10 11.88,23.19 v1(12.19,23.5)
  BOTTOM w0.305: v1(40.39,24.49) 40.39,24.38 40.14,24.14 R178.1 ; D14.1 v1(9.81,19.56) ; C201.1 41.54,27.37 41.29,27.62 41.29,27.93 v1(41.15,28.07) ; U40.3 72.78,48.73 v1(72.54,48.49) 72.13,48.9 U40.2 ; D15.1 v1(11.34,19.56) ; C133.2 62.32,47.23 U16.2 60.47,47.23 v1(60.2,47.5) ; v1(100.7,98.54) C237.1 C235.2 ; 95.94,70.97 95.94,70.99 ; v1(78.87,48.34) 78.63,48.57 U40.12 ; C190.1 v1(99.06,92.58) ; C187.2 v1(101.09,93.34)
  BOTTOM w0.356: C200.2 C201.1
  BOTTOM w0.406: C98.1 28.96,91.69 v1(28.7,91.95)
  BOTTOM w0.457: v2(47.24,15.24) 46.99,15.24 46.87,15.12 C23.1
  BOTTOM w0.508: 111.09,30.86 J3.4 ; J3.4 113.96,30.86 ; J3.4 112.52,32.3 ; J3.4 112.52,29.43 ; 112.52,67.94 J1.4 ; J1.4 111.09,69.37 ; J1.4 113.96,69.37 ; J1.4 112.52,70.81 ; C232.2 85.73,15.53 v1(85.46,15.26) R306.1 ; 50.42,5.68 P9.1 ; P9.1 51.6,6.86 ; P9.1 50.42,8.04 ; C197.1 40.39,15.78 40.94,16.33 41.04,16.33 v2(41.08,16.37) 40.77,16.68 C194.2 ; J3.2 112.52,37.38 ; J3.2 112.52,34.51 ; J3.2 111.09,35.94 ; J3.2 113.96,35.94 ; J4.2 113.83,14.99 ; J4.2 110.96,14.99 ; J4.2 112.39,13.55 ; J4.2 112.39,16.42 ; C233.2 70.56,41.92 ; C233.2 69.98,40.28 v1(70.31,39.95) ; C233.2 69.39,41.92 ; 117.6,73.02 J1.3 ; J1.3 117.6,75.89 ; J1.3 116.17,74.45 ; P11.4 39.54,78.36 ; P11.4 38.35,77.18 ; P11.4 37.17,78.36 ; P11.4 38.35,79.54 ; 1.29,89.14 P5.3 ; P5.3 2.54,90.38 ; P5.3 2.54,87.89 ; P5.3 3.79,89.14 ; v1(42.67,29.85) 42.68,29.85 42.87,29.85 43.03,29.68 R189.1 ; 57.44,45.08 C140.2 C143.2 ; C162.2 46.63,20.35 v2(46.68,20.4) ; C5.1 v1(65.76,46.59) ; 104.99,30.86 P3.1 ; P3.1 106.17,32.04 ; P3.1 107.35,30.86 ; P3.1 106.17,29.68 ; 106.17,68.19 P1.1 ; P1.1 107.35,69.37 ; P1.1 104.99,69.37 ; P1.1 106.17,70.55 ; C164.2 C163.2 46.49,55.53 v1(46.31,55.34) ; 68.54,51.41 C11.1 67.95,51.96 ; C133.2 C132.2 v1(64.11,47.5) ; 2.54,13.23 S2.1 ; S2.1 1.42,14.35 ; S2.1 3.66,14.35 ; S2.1 2.54,15.47 ; P11.9 47.16,75.82 ; P11.9 44.79,75.82 ; P11.9 45.97,77 ; P11.9 45.97,74.64 ; P14.3 3.79,72.38 ; P14.3 2.54,73.62 ; P14.3 1.29,72.38 ; P14.3 2.54,71.13 ; 36.7,3.14 P10.5 ; P10.5 36.7,5.5 ; P10.5 37.88,4.32 ; P11.3 38.35,77 ; P11.3 37.17,75.82 ; P11.3 39.54,75.82 ; P11.3 38.35,74.64 ; R344.1 76.95,86.88 ; R344.1 75.7,86.88 ; R344.1 76.33,86.3 ; C150.1 38.19,23.16 v1(37.59,23.75) ; R316.1 v1(6.73,23.6) ; C4.1 65.49,49 ; C4.1 v1(64.91,49.66) ; C4.1 64.32,49 ; C8.1 v1(65.76,44.3) ; C8.1 64.91,44.85 ; C8.1 64.32,44.3 ; v1(37.59,14.33) 37.59,14.48 37.6,14.49 C139.2 R187.1 ; J1.2 113.96,74.45 ; J1.2 112.52,75.89 ; J1.2 111.09,74.45 ; J1.2 112.52,73.02 ; 35.52,6.86 36.7,6.86 ; 36.7,6.86 36.7,8.04 ; 36.7,6.86 36.7,5.68 ; C7.1 v1(67.1,46.59) ; C7.1 68.54,46.59 ; C7.1 67.95,47.13 ; 106.81,98.01 J6.2 ; J6.2 107.86,99.06 ; J6.2 105.75,99.06 ; J6.2 106.81,100.11 ; C228.2 85.73,54.04 v1(85.46,53.78) R303.1 ; J3.3 117.6,37.38 ; J3.3 116.17,35.94 ; J3.3 117.6,34.51 ; 29.54,90.92 C98.1 28.37,90.92 ; C226.2 85.85,74.99 v1(85.59,74.73) R302.1 ; C263.2 86.77,76.37 v1(86.76,76.36) ; C263.2 88.34,76.37 ; C263.2 87.76,76.91 ; 22.89,64.76 R295.2 ; R295.2 22.89,66 ; R295.2 22.1,65.38 v1(21.84,65.63) ; J2.4 113.83,48.42 ; J2.4 112.39,49.85 ; J2.4 110.96,48.42 ; J2.4 112.39,46.98 ; v1(45.47,44.83) 44.96,44.83 44.19,44.06 C168.1 C167.1 ; C170.1 41.94,20.35 v2(41.88,20.4) ; C265.2 87.76,38.4 ; C265.2 88.34,37.85 ; C265.2 86.77,37.85 v1(86.76,37.85) ; C10.1 68.54,44.3 ; C10.1 v1(67.1,44.3) ; C10.1 67.95,44.85 ; 64.32,51.41 C9.1 ; C9.1 65.49,51.41 ; C9.1 v1(64.91,52.45) ; P4.1 106.05,11.09 ; P4.1 106.05,8.72 ; P4.1 104.86,9.91 ; P4.1 107.23,9.91 ; C161.2 41.79,22.09 v2(41.88,22) ; 45.97,77.18 P11.10 ; P11.10 45.97,79.54 ; P11.10 44.79,78.36 ; P11.10 47.16,78.36 ; P12.2 4.06,60.05 ; P12.2 4.06,57.56 ; P12.2 2.82,58.8 ; P12.2 5.31,58.8 ; J4.4 113.83,9.91 ; J4.4 110.96,9.91 ; J4.4 112.39,8.47 ; J4.4 112.39,11.34 ; C259.1 13.58,20.84 C256.2 v1(12.61,20.18) ; R87.1 v1(27.05,101.09) ; 116.17,30.86 J3.5 ; J3.5 117.6,29.43 ; J3.5 117.6,32.3 ; C146.1 61.64,51.28 ; C146.1 v1(61.64,49.56) ; C146.1 62.37,50.53 ; 79.05,49.86 U40.12 78.63,51 ; v1(49.15,47.62) 48.77,47.62 48.26,48.13 C166.2 ; v1(86.64,55.4) 86.65,55.41 C264.2 ; P2.1 106.05,49.6 ; P2.1 106.05,47.24 ; P2.1 107.23,48.42 ; P2.1 104.86,48.42 ; v1(23.01,100.84) 22.48,100.31 R83.1 R85.1 ; C156.2 40.02,19.03 38.97,19.03 C149.1 37.71,19.14 37.29,19.56 v1(36.58,19.56) ; C165.2 49.79,48.78 v1(50.15,49.14) ; C6.1 68.54,49 ; C6.1 v1(66.9,49) ; C6.1 67.95,49.55 ; C231.2 85.85,36.48 v1(85.59,36.22) R307.1 ; 110.96,53.5 J2.2 ; J2.2 112.39,54.93 ; J2.2 113.83,53.5 ; J2.2 112.39,52.06 ; J1.5 117.6,70.81 ; J1.5 117.6,67.94 ; J1.5 116.17,69.37 ; 117.48,52.06 J2.3 ; J2.3 117.48,54.93 ; J2.3 116.04,53.5 ; 117.48,8.47 J4.5 ; J4.5 117.48,11.34 ; J4.5 116.04,9.91 ; v1(86.64,16.89) 86.65,16.9 C266.2 ; 116.04,14.99 J4.3 ; J4.3 117.48,13.55 ; J4.3 117.48,16.42 ; 116.04,48.42 J2.5 ; J2.5 117.48,46.98 ; J2.5 117.48,49.85 ; 11.95,20.22 D15.1 10.72,20.22 ; R292.1 v1(6.77,21.5)
  vias: v1(1.08,100.97) v1(1.08,99.38) v1(1.08,97.79) v1(1.08,96.2) v1(1.08,94.61) v1(1.08,93.03) v1(1.08,91.44) v1(1.08,89.85) v1(1.08,88.27) v1(1.08,86.68) v1(1.08,83.5) v1(1.08,81.91) v1(1.08,75.56) v1(1.08,73.98) v1(1.08,72.39) v1(1.08,70.8) v1(1.08,69.22) v1(1.08,67.63) v1(1.08,66.04) v1(1.08,64.45) v1(1.08,62.99) v1(1.08,61.4) v1(1.08,59.82) v1(1.08,58.23) v1(1.08,56.64) v1(1.08,55.05) v1(1.08,53.47) v1(1.08,51.88) v1(1.08,50.29) v1(1.08,48.7) v1(1.08,47.12) v1(1.08,45.53) v1(1.08,23.24) v1(1.08,21.65) v1(1.08,20.19) v1(1.08,18.61) v1(1.08,17.02) v1(1.08,15.43) v1(1.08,13.84) v1(1.08,12.26) v1(1.08,10.67) v1(1.08,9.08) v1(1.08,7.49) v1(1.08,5.91) v1(1.08,4.32) v1(1.08,2.73) v1(1.27,102.36) v1(1.27,44.45) v1(1.27,0.95) v1(2.41,51.18) v1(2.41,50.54) v1(2.86,0.95) v1(3.05,51.18) v1(3.05,50.54) v1(3.68,51.18) v1(3.68,50.54) v1(4.45,0.95) v1(5.59,44.83) v1(5.59,44.07) v1(5.61,43.31) v1(6.03,0.95) v1(6.67,103.31) v1(7.62,0.95) v1(8.26,103.31) v1(9.21,0.95) v1(9.53,58.8) v1(9.84,103.31) v1(10.41,27.94) v1(10.79,0.95) v1(11.05,61.34) v1(11.43,103.31) v1(12.32,31.12) v1(12.38,0.95) v1(12.57,61.34) v1(13.02,103.31) v1(13.97,0.95) v1(14.21,28.32) v1(14.48,15.11) v1(14.48,13.84) v1(14.61,103.31) v1(14.61,41.53) v1(14.61,40.77) v1(14.61,40) v1(14.99,14.48) v1(15.49,15.11) v1(15.49,13.84) v1(15.56,0.95) v1(16.19,103.31) v1(16.26,58.67) v1(17.14,33.15) v1(17.14,0.95) v1(17.4,76.71) v1(17.4,31.37) v1(17.78,103.31) v1(18.16,33.15) v1(18.29,30.48) v1(18.54,31.37) v1(18.73,0.95) v1(18.92,25.53) v1(18.92,18.29) v1(18.92,17.53) v1(19.18,81.15) v1(19.18,33.15) v1(19.3,28.07) v1(19.37,103.31) v1(19.74,65.63) v1(19.68,64.54) v1(19.68,63.55) v1(19.68,62.56) v1(19.68,61.59) v1(19.68,31.37) v1(20.19,80.39) v1(20.19,33.15) v1(20.45,30.1) v1(20.45,25.53) v1(20.57,15.75) v1(20.83,65.63) v1(20.78,64.54) v1(20.78,63.55) v1(20.78,62.56) v1(20.78,61.59) v1(20.83,31.37) v1(20.95,103.31) v1(21.37,37.81) v1(21.46,33.15) v1(21.46,15.75) v1(21.72,77.47) v1(21.79,64.54) v1(21.79,63.55) v1(21.79,62.56) v1(21.79,61.59) v1(22.1,31.37) v1(22.54,103.31) v1(22.48,29.97) v1(22.48,28.19) v1(22.61,33.15) v1(22.86,23.88) v1(22.99,22.23) v1(22.99,20.96) v1(23.24,31.37) v1(23.37,20.07) v1(23.49,67.31) v1(23.88,33.15) v1(24.13,103.31) v1(24.13,19.3) v1(24.51,31.37) v1(24.77,71.12) v1(24.76,23.88) v1(24.89,43.31) v1(25.15,33.15) v1(25.21,0.95) v1(25.53,43.97) v1(25.65,31.37) v1(25.72,103.31) v1(26.16,33.15) v1(26.29,70.1) v1(26.8,0.95) v1(26.92,94.23) v1(26.92,93.47) v1(26.92,92.71) v1(26.92,91.95) v1(27.05,70.1) v1(27.05,26.42) v1(27.3,103.31) v1(27.3,18.03) v1(27.43,13.21) v1(27.56,19.81) v1(27.69,40.77) v1(27.69,22.23) v1(27.73,15.62) v1(27.73,14.73) v1(27.81,94.23) v1(27.81,93.47) v1(27.81,92.71) v1(27.81,91.95) v1(27.81,70.1) v1(28.19,76.96) v1(28.19,22.86) v1(28.45,26.42) v1(28.45,15.62) v1(28.45,14.73) v1(28.38,0.95) v1(28.7,94.23) v1(28.7,93.47) v1(28.7,92.71) v1(28.7,28.96) v1(28.7,21.34) v1(28.83,76.96) v1(28.83,51.43) v1(28.89,103.31) v1(28.96,34.8) v1(28.96,13.21) v1(29.02,22.84) v1(29.34,26.42) v1(29.34,18.03) v1(29.46,94.23) v1(29.46,93.47) v1(29.46,92.71) v1(29.46,91.95) v1(29.46,76.96) v1(29.46,28.19) v1(29.72,38.1) v1(29.97,30.23) v1(30.02,22.84) v1(29.97,21.21) v1(29.97,0.95) v1(30.1,50.42) v1(30.1,26.42) v1(30.23,94.23) v1(30.23,93.47) v1(30.23,92.71) v1(30.23,91.95) v1(30.23,76.07) v1(30.48,103.31) v1(30.61,29.59) v1(30.93,22.84) v1(30.99,76.07) v1(31.56,0.95) v1(31.74,30.47) v1(31.74,29.66) v1(31.88,26.42) v1(32,76.33) v1(32.07,103.31) v1(32.26,47.24) v1(32.51,49.53) v1(33.02,76.33) v1(33.07,26.42) v1(33.06,22.92) v1(33.15,0.95) v1(33.4,43.69) v1(33.66,103.31) v1(33.6,27.85) v1(33.83,31.24) v1(33.91,94.36) v1(33.91,93.62) v1(34.42,40.89) v1(34.42,25.78) v1(34.44,25.02) v1(34.67,94.36) v1(34.67,93.6) v1(34.73,0.95) v1(35.05,81.79) v1(35.24,103.31) v1(35.43,94.36) v1(35.43,93.6) v1(35.56,19.56) v1(35.84,26.72) v1(35.89,27.41) v1(36.16,72.17) v1(36.32,0.95) v1(36.55,30.84) v1(36.83,103.31) v1(37.08,96.9) v1(37.91,0.95) v1(38.1,96.9) v1(38.42,103.31) v1(39.5,0.95) v1(40.01,103.31) v1(40.39,34.34) v1(40.51,69.34) v1(40.51,67.94) v1(40.51,66.67) v1(40.63,35.57) v1(41.08,0.95) v1(41.4,69.34) v1(41.4,67.94) v1(41.4,66.67) v1(41.59,103.31) v1(42.29,69.34) v1(42.29,67.94) v1(42.29,66.67) v1(42.67,92.96) v1(42.67,81.79) v1(42.67,0.95) v1(43.18,103.31) v1(43.56,92.96) v1(43.69,97.92) v1(43.69,72.39) v1(44.26,0.95) v1(44.32,97.92) v1(44.32,71.25) v1(44.45,38.73) v1(44.7,92.84) v1(44.77,103.31) v1(45.09,38.22) v1(45.47,65.28) v1(45.59,92.84) v1(45.85,0.95) v1(46.36,103.31) v1(46.36,92.18) v1(46.48,81.79) v1(46.86,37.21) v1(47.43,0.95) v1(47.5,36.58) v1(47.94,103.31) v1(49.02,0.95) v1(49.53,103.31) v1(50.48,0.95) v1(51.12,103.31) v1(52.07,0.95) v1(52.71,103.31) v1(53.66,0.95) v1(54.1,97.03) v1(54.29,103.31) v1(55.25,0.95) v1(55.88,103.31) v1(56.83,0.95) v1(57.47,103.31) v1(57.91,100.84) v1(58.42,0.95) v1(59.05,103.31) v1(59.2,47.48) v1(59.18,46.48) v1(60.01,0.95) v1(60.2,46.48) v1(60.64,103.31) v1(61.09,14.1) v1(61.59,0.95) v1(61.72,100.84) v1(62.1,84.2) v1(62.1,83.06) v1(62.23,103.31) v1(62.36,85.22) v1(62.36,82.04) v1(62.99,81.15) v1(63.12,85.98) v1(63.09,82.81) v1(63.18,0.95) v1(63.5,48.77) v1(63.75,80.26) v1(63.82,103.31) v1(63.88,82.04) v1(63.88,53.85) v1(63.88,52.58) v1(63.88,51.43) v1(63.88,49.78) v1(64.01,16.13) v1(64.26,86.11) v1(64.52,79.63) v1(64.64,72.77) v1(64.77,38.86) v1(64.77,0.95) v1(64.9,82.04) v1(65.15,73.66) v1(65.28,86.11) v1(65.41,103.31) v1(65.53,100.84) v1(65.79,80.9) v1(66.17,79.5) v1(66.17,74.8) v1(66.36,0.9) v1(66.42,86.11) v1(66.42,54.86) v1(66.42,53.72) v1(66.67,71.37) v1(66.67,70.23) v1(66.8,52.07) v1(66.8,32.51) v1(66.8,16.38) v1(66.8,15.37) v1(66.93,75.69) v1(66.93,37.08) v1(66.99,103.31) v1(67.18,80.52) v1(67.18,57.15) v1(67.18,55.63) v1(67.31,69.34) v1(67.31,38.1) v1(67.44,17.02) v1(67.56,86.11) v1(67.69,30.99) v1(67.95,0.9) v1(68.07,79.5) v1(68.2,10.03) v1(68.33,76.83) v1(68.33,58.93) v1(68.33,57.15) v1(68.33,55.63) v1(68.45,69.34) v1(68.58,103.31) v1(68.71,86.11) v1(68.83,46.61) v1(68.96,30.99) v1(69.09,80.52) v1(69.22,77.6) v1(69.34,100.84) v1(69.34,10.03) v1(69.47,76.58) v1(69.47,29.97) v1(69.47,27.69) v1(69.47,25.65) v1(69.47,23.37) v1(69.47,21.21) v1(69.47,18.92) v1(69.53,0.9) v1(69.85,86.11) v1(69.98,78.49) v1(70.1,46.61) v1(70.17,103.31) v1(70.36,95) v1(70.36,28.96) v1(70.36,26.67) v1(70.36,24.64) v1(70.36,22.35) v1(70.36,20.19) v1(70.36,17.91) v1(70.43,70.64) v1(70.48,10.03) v1(70.61,79.25) v1(70.61,69.34) v1(70.61,59.82) v1(70.61,32.13) v1(70.61,30.86) v1(70.87,88.91) v1(70.87,86.74) v1(70.87,76.99) v1(70.99,23.62) v1(70.99,21.34) v1(71.13,96.78) v1(71.12,27.56) v1(71.12,25.27) v1(71.12,0.9) v1(71.24,85.97) v1(71.25,57.91) v1(71.37,10.67) v1(71.5,60.71) v1(71.75,103.31) v1(71.75,70.48) v1(71.75,69.34) v1(71.88,88.14) v1(71.88,79.25) v1(71.88,30.86) v1(71.88,22.61) v1(71.88,20.32) v1(72.01,87) v1(72.01,26.54) v1(72.01,24.26) v1(72.14,75.06) v1(72.14,58.67) v1(72.26,78.11) v1(72.39,10.92) v1(72.71,0.9) v1(72.9,88.14) v1(73.03,87) v1(73.15,79.25) v1(73.34,103.31) v1(73.53,52.59) v1(73.53,51.83) v1(73.53,23.37) v1(73.53,21.08) v1(73.53,14.08) v1(73.53,13.07) v1(73.53,10.92) v1(73.66,73.55) v1(73.66,72.53) v1(73.66,48.39) v1(73.66,35.04) v1(73.66,34.02) v1(73.66,27.94) v1(73.66,25.65) v1(73.79,32.13) v1(73.79,29.85) v1(74.04,88.52) v1(74.04,87.38) v1(74.04,70.48) v1(74.04,69.34) v1(74.3,0.9) v1(74.42,79.25) v1(74.42,22.35) v1(74.42,20.07) v1(74.55,61.21) v1(74.55,59.56) v1(74.56,52.6) v1(74.55,51.83) v1(74.55,26.92) v1(74.55,24.64) v1(74.56,14.09) v1(74.55,13.07) v1(74.69,73.56) v1(74.68,72.53) v1(74.69,35.05) v1(74.68,34.02) v1(74.68,31.12) v1(74.68,28.83) v1(74.68,10.92) v1(74.93,103.31) v1(75.06,88.52) v1(75.06,87.38) v1(75.18,70.48) v1(75.18,69.34) v1(75.31,77.22) v1(75.56,71.5) v1(75.69,79.25) v1(75.69,74.68) v1(75.69,63.63) v1(75.69,61.21) v1(75.69,59.56) v1(75.69,15.62) v1(75.82,76.2) v1(75.82,37.21) v1(75.82,10.92) v1(75.88,0.9) v1(76.33,69.34) v1(76.45,77.22) v1(76.45,70.74) v1(76.52,103.31) v1(76.58,75.44) v1(76.71,16.13) v1(76.84,63.63) v1(76.84,61.21) v1(76.84,59.56) v1(76.96,79.25) v1(76.96,10.92) v1(77.22,69.98) v1(77.47,0.9) v1(77.6,77.22) v1(77.6,75.82) v1(77.6,68.83) v1(77.85,16.26) v1(77.98,63.63) v1(77.98,61.21) v1(77.98,59.56) v1(77.98,10.79) v1(78.11,103.31) v1(78.23,79.25) v1(78.23,69.72) v1(78.61,37.34) v1(78.61,31.62) v1(78.74,77.22) v1(78.74,75.95) v1(78.99,80.39) v1(78.99,16.38) v1(78.99,10.67) v1(79.06,0.9) v1(79.12,68.96) v1(79.12,63.63) v1(79.12,61.21) v1(79.12,59.56) v1(79.12,25.15) v1(79.25,29.85) v1(79.25,27.56) v1(79.25,22.99) v1(79.5,79.25) v1(79.5,49.15) v1(79.69,103.31) v1(79.76,70.2) v1(79.76,37.34) v1(79.76,31.62) v1(79.88,81.15) v1(80.01,24.13) v1(80.14,28.83) v1(80.14,26.54) v1(80.14,21.97) v1(80.26,68.96) v1(80.26,63.63) v1(80.26,61.21) v1(80.26,59.56) v1(80.26,58.29) v1(80.52,49.66) v1(80.64,81.91) v1(80.64,11.05) v1(80.64,0.9) v1(80.77,79.25) v1(80.9,82.93) v1(80.9,70.23) v1(80.9,31.62) v1(80.9,25.15) v1(81.03,29.85) v1(81.03,27.56) v1(81.03,22.99) v1(81.15,84.45) v1(81.28,103.31) v1(81.28,39.5) v1(81.28,20.57) v1(81.41,71.12) v1(81.41,68.96) v1(81.41,63.63) v1(81.41,61.21) v1(81.41,59.56) v1(81.41,58.29) v1(81.41,49.66) v1(81.53,40.51) v1(81.66,11.68) v1(81.66,7.11) v1(81.79,83.57) v1(81.79,31.62) v1(81.92,79.12) v1(82.04,70.23) v1(82.04,49.91) v1(82.04,24.13) v1(82.17,28.83) v1(82.17,26.54) v1(82.17,21.97) v1(82.23,0.9) v1(82.55,68.96) v1(82.55,63.63) v1(82.55,61.21) v1(82.55,59.56) v1(82.55,58.29) v1(82.55,20.57) v1(82.65,30.86) v1(82.8,84.05) v1(82.8,82.93) v1(82.8,25.15) v1(82.8,11.68) v1(82.8,7.11) v1(82.87,103.31) v1(82.93,78.99) v1(82.93,29.85) v1(82.93,27.56) v1(82.93,22.99) v1(83.31,68.07) v1(83.57,40.51) v1(83.69,63.63) v1(83.69,61.21) v1(83.69,59.56) v1(83.69,58.29) v1(83.82,84.05) v1(83.82,24.13) v1(83.82,20.57) v1(83.82,0.9) v1(83.95,82.93) v1(83.95,47.62) v1(83.95,45.59) v1(83.95,28.83) v1(83.95,26.54) v1(83.95,21.97) v1(83.95,11.68) v1(83.95,7.11) v1(84.07,78.99) v1(84.2,67.44) v1(84.33,68.73) v1(84.45,103.31) v1(84.45,71.12) v1(84.45,25.15) v1(84.58,44.7) v1(84.58,29.85) v1(84.58,27.56) v1(84.58,22.99) v1(84.71,40.51) v1(84.84,83.57) v1(84.84,66.42) v1(84.84,63.63) v1(84.84,61.21) v1(84.84,59.56) v1(84.84,58.29) v1(84.84,6.98) v1(84.88,41.76) v1(85.09,20.57) v1(85.22,78.99) v1(85.34,43.94) v1(85.34,9.78) v1(85.41,0.9) v1(85.6,84.33) v1(85.6,65.66) v1(85.6,64.52) v1(85.73,42.8) v1(85.73,25.15) v1(85.85,40.51) v1(85.85,6.73) v1(85.94,66.42) v1(85.94,45.47) v1(86.04,103.31) v1(86.07,27.69) v1(86.23,30.82) v1(86.36,78.99) v1(86.61,84.45) v1(86.74,69.47) v1(86.74,48.39) v1(87.12,79.76) v1(87.12,0.89) v1(87.38,78.61) v1(87.38,41.53) v1(87.38,24.38) v1(87.63,103.31) v1(87.63,84.71) v1(87.63,80.9) v1(88.39,85.6) v1(88.65,81.03) v1(88.65,46.09) v1(88.65,44.58) v1(88.65,43.43) v1(88.58,0.95) v1(88.77,30.73) v1(88.77,29.59) v1(88.77,28.45) v1(88.77,27.3) v1(88.77,26.16) v1(88.9,25.02) v1(89.03,46.99) v1(89.15,42.54) v1(89.15,6.86) v1(89.22,103.31) v1(89.28,68.45) v1(89.28,67.31) v1(89.28,65.02) v1(89.28,64.01) v1(89.28,49.15) v1(89.28,48.01) v1(89.44,66.29) v1(89.41,61.21) v1(89.41,59.94) v1(89.66,86.87) v1(89.66,84.96) v1(89.66,30.1) v1(89.79,81.03) v1(89.79,21.34) v1(90.04,7.62) v1(90.17,0.95) v1(90.3,47.75) v1(90.42,68.45) v1(90.42,67.31) v1(90.42,66.17) v1(90.42,65.02) v1(90.42,64.01) v1(90.55,61.21) v1(90.55,59.94) v1(90.68,29.97) v1(90.68,28.83) v1(90.68,27.69) v1(90.68,26.54) v1(90.68,25.4) v1(90.68,24.26) v1(90.68,23.11) v1(90.81,103.31) v1(90.81,8.38) v1(90.93,84.96) v1(90.93,81.03) v1(90.93,21.34) v1(91.57,9.14) v1(91.76,0.95) v1(92.08,81.03) v1(92.08,47.5) v1(92.2,84.96) v1(92.2,66.17) v1(92.33,26.54) v1(92.33,25.4) v1(92.33,24.26) v1(92.33,23.11) v1(92.39,103.31) v1(92.84,86.87) v1(92.84,80.01) v1(92.84,78.87) v1(92.84,77.09) v1(92.96,64.39) v1(93.09,97.92) v1(93.09,62.86) v1(93.22,61.47) v1(93.34,0.95) v1(93.47,84.96) v1(93.6,24.26) v1(93.6,22.99) v1(93.73,78.23) v1(93.98,103.31) v1(93.98,77.22) v1(93.98,52.83) v1(93.98,51.94) v1(93.98,50.93) v1(93.98,14.32) v1(93.98,13.43) v1(93.98,12.42) v1(94.11,86.23) v1(94.11,73.79) v1(94.11,72.9) v1(94.11,71.88) v1(94.11,35.28) v1(94.11,34.39) v1(94.11,33.37) v1(94.36,62.61) v1(94.36,61.47) v1(94.49,42.29) v1(94.49,40) v1(94.62,46.74) v1(94.62,44.45) v1(94.74,87.5) v1(94.74,84.96) v1(94.74,9.14) v1(94.87,52.83) v1(94.87,51.94) v1(94.87,50.93) v1(94.87,14.32) v1(94.87,13.43) v1(94.87,12.42) v1(94.93,0.95) v1(95,73.79) v1(95,72.9) v1(95,71.88) v1(95,35.28) v1(95,34.39) v1(95,33.37) v1(95.12,77.22) v1(95.38,86.23) v1(95.38,47.62) v1(95.38,41.27) v1(95.38,38.99) v1(95.5,87.5) v1(95.5,84.96) v1(95.5,45.72) v1(95.5,43.43) v1(95.57,103.31) v1(95.76,62.61) v1(95.76,61.47) v1(95.76,24.13) v1(95.76,22.99) v1(95.89,52.83) v1(95.89,51.94) v1(95.89,50.93) v1(95.89,14.32) v1(95.89,13.43) v1(95.89,12.42) v1(95.89,9.14) v1(95.89,6.6) v1(96.01,73.79) v1(96.01,72.9) v1(96.01,71.88) v1(96.01,35.28) v1(96.01,34.39) v1(96.01,33.37) v1(96.27,77.22) v1(96.39,48.13) v1(96.39,46.74) v1(96.39,44.45) v1(96.39,42.42) v1(96.39,40.13) v1(96.52,0.95) v1(96.65,86.23) v1(96.65,30.99) v1(96.65,9.91) v1(96.77,61.21) v1(96.77,11.62) v1(96.9,71.06) v1(96.9,62.61) v1(96.9,24.13) v1(96.9,22.35) v1(96.9,5.97) v1(97.03,50.1) v1(97.03,49.02) v1(97.03,32.45) v1(97.16,103.31) v1(97.28,87.5) v1(97.28,84.96) v1(97.28,45.72) v1(97.28,43.43) v1(97.28,41.4) v1(97.28,39.12) v1(97.41,77.22) v1(97.41,10.79) v1(97.79,30.99) v1(97.79,5.33) v1(97.92,86.23) v1(97.92,61.09) v1(98.04,62.61) v1(98.04,24.13) v1(98.04,22.35) v1(98.11,0.95) v1(98.17,71.12) v1(98.17,60.2) v1(98.17,50.16) v1(98.17,49.02) v1(98.17,46.74) v1(98.17,44.45) v1(98.17,42.29) v1(98.17,40) v1(98.17,32.38) v1(98.23,11.62) v1(98.3,76.71) v1(98.3,29.97) v1(98.55,87.5) v1(98.55,84.96) v1(98.93,21.34) v1(98.93,5.33) v1(99.06,10.79) v1(99.19,86.23) v1(99.19,62.99) v1(99.19,45.72) v1(99.19,43.43) v1(99.19,41.27) v1(99.19,38.99) v1(99.19,24.13) v1(99.57,49.02) v1(99.7,59.82) v1(99.7,0.95) v1(99.82,87.5) v1(99.82,84.96) v1(99.82,76.71) v1(99.82,11.62) v1(99.95,71.06) v1(99.95,46.74) v1(99.95,44.45) v1(99.95,42.29) v1(99.95,40) v1(99.95,29.59) v1(100.08,50.1) v1(100.08,32.45) v1(100.08,21.34) v1(100.08,5.33) v1(100.46,86.23) v1(100.46,24.38) v1(100.59,16) v1(100.58,6.22) v1(100.71,63.12) v1(100.84,66.42) v1(100.84,49.02) v1(100.84,20.57) v1(101.09,87.5) v1(101.09,84.96) v1(101.09,58.55) v1(101.09,29.59) v1(101.09,28.19) v1(101.35,45.72) v1(101.35,43.43) v1(101.35,41.27) v1(101.35,39.12) v1(101.28,0.95) v1(101.41,37.66) v1(101.41,36) v1(101.41,11.62) v1(101.47,56.26) v1(101.54,25.53) v1(101.6,76.83) v1(101.73,86.23) v1(101.66,50.1) v1(101.66,32.45) v1(101.73,6.22) v1(101.92,103.31) v1(102.23,75.95) v1(102.23,58.55) v1(102.36,87.5) v1(102.36,84.96) v1(102.36,49.02) v1(102.36,46.74) v1(102.36,44.45) v1(102.36,42.29) v1(102.36,40) v1(102.36,27.81) v1(102.36,23.11) v1(102.36,20.07) v1(102.36,14.99) v1(102.49,81.91) v1(102.49,79.12) v1(102.49,60.83) v1(102.49,57.28) v1(102.49,18.8) v1(102.62,66.29) v1(102.74,61.59) v1(102.87,53.53) v1(102.87,6.22) v1(102.87,0.95) v1(103,86.23) v1(103,74.49) v1(103,71.06) v1(103,45.72) v1(103,43.43) v1(103,41.27) v1(103,38.99) v1(103,37.66) v1(103,36) v1(103.12,83.19) v1(103.12,80.39) v1(103.12,50.1) v1(103.12,32.45) v1(103.25,14.99) v1(103.38,75.95) v1(103.38,58.55) v1(103.38,19.94) v1(103.5,103.31) v1(103.5,27.81) v1(103.5,23.24) v1(103.63,87.5) v1(103.63,84.96) v1(103.63,49.02) v1(103.63,11.56) v1(103.76,81.91) v1(103.76,79.12) v1(103.76,66.29) v1(103.76,61.85) v1(103.89,24.26) v1(104.01,42.29) v1(104.01,40) v1(104.01,6.22) v1(104.14,98.04) v1(104.14,93.35) v1(104.14,46.74) v1(104.14,44.45) v1(104.27,86.23) v1(104.27,57.91) v1(104.27,19.3) v1(104.39,83.19) v1(104.39,80.39) v1(104.46,71.06) v1(104.46,53.53) v1(104.46,14.92) v1(104.46,0.95) v1(104.52,75.95) v1(104.58,74.49) v1(104.58,50.1) v1(104.58,37.66) v1(104.58,36) v1(104.58,32.45) v1(104.65,27.81) v1(104.65,7.11) v1(104.78,8.13) v1(104.9,87.5) v1(104.9,84.96) v1(104.9,66.29) v1(104.9,62.36) v1(104.9,41.27) v1(104.9,38.99) v1(104.9,11.56) v1(105.03,81.91) v1(105.03,79.12) v1(105.03,45.72) v1(105.03,43.43) v1(105.03,24.26) v1(105.09,103.31) v1(105.28,20.07) v1(105.41,57.91) v1(105.54,86.23) v1(105.66,83.19) v1(105.66,80.39) v1(105.66,42.29) v1(105.66,40) v1(105.79,44.45) v1(105.79,27.81) v1(105.92,62.48) v1(105.92,8.13) v1(106.05,66.29) v1(106.05,53.53) v1(106.05,14.92) v1(106.05,0.95) v1(106.17,87.5) v1(106.17,84.96) v1(106.17,76.01) v1(106.17,74.49) v1(106.17,37.66) v1(106.17,36) v1(106.17,24.26) v1(106.3,81.91) v1(106.3,79.12) v1(106.55,57.91) v1(106.55,41.27) v1(106.55,38.99) v1(106.55,26.54) v1(106.55,25.78) v1(106.68,103.31) v1(106.68,56.64) v1(106.68,55.88) v1(106.68,45.72) v1(106.68,43.43) v1(106.68,18.16) v1(106.68,17.4) v1(106.81,86.23) v1(106.93,83.19) v1(106.93,80.39) v1(106.93,65.02) v1(107.06,8.13) v1(107.19,66.29) v1(107.19,62.48) v1(107.44,87.5) v1(107.44,84.96) v1(107.44,19.43) v1(107.57,81.91) v1(107.57,79.12) v1(107.63,71.06) v1(107.63,53.53) v1(107.63,14.92) v1(107.63,0.95) v1(107.76,76.01) v1(107.76,74.49) v1(107.7,57.91) v1(107.76,50.1) v1(107.76,37.66) v1(107.76,36) v1(107.76,32.45) v1(107.82,7.37) v1(108.08,86.23) v1(108.08,27.81) v1(108.2,83.19) v1(108.2,80.39) v1(108.27,103.31) v1(108.33,66.29) v1(108.59,19.43) v1(108.71,87.5) v1(108.71,84.96) v1(108.84,81.91) v1(108.84,79.12) v1(108.84,57.91) v1(108.84,56.9) v1(108.84,26.67) v1(108.84,18.29) v1(108.84,16.64) v1(108.97,62.48) v1(108.97,24.26) v1(109.09,65.15) v1(109.09,63.5) v1(109.09,7.11) v1(109.22,53.53) v1(109.22,45.59) v1(109.22,41.66) v1(109.22,39.37) v1(109.22,27.81) v1(109.22,14.92) v1(109.22,0.95) v1(109.35,86.23) v1(109.35,76.01) v1(109.35,74.49) v1(109.35,43.81) v1(109.35,37.66) v1(109.35,36) v1(109.47,83.19) v1(109.47,80.39) v1(109.47,66.29) v1(109.47,59.05) v1(109.6,61.21) v1(109.73,19.43) v1(109.86,103.31) v1(109.98,87.5) v1(109.98,84.96) v1(109.98,57.91) v1(109.98,54.48) v1(110.11,81.91) v1(110.11,79.12) v1(110.11,40.64) v1(110.11,24.26) v1(110.24,62.48) v1(110.24,42.8) v1(110.24,7.11) v1(110.36,45.59) v1(110.36,27.81) v1(110.49,60.2) v1(110.62,86.23) v1(110.62,66.29) v1(110.74,83.19) v1(110.74,80.39) v1(110.81,53.53) v1(110.81,14.92) v1(110.81,0.95) v1(110.93,76.01) v1(110.93,74.49) v1(110.93,37.66) v1(110.93,36) v1(110.87,19.43) v1(111,23.37) v1(111,21.08) v1(111.12,57.91) v1(111.12,43.81) v1(111.12,41.78) v1(111.12,39.5) v1(111.12,7.75) v1(111.25,87.5) v1(111.25,84.96) v1(111.25,24.26) v1(111.44,103.31) v1(111.38,81.91) v1(111.38,79.12) v1(111.38,62.48) v1(111.38,61.21) v1(111.38,59.18) v1(111.38,46.1) v1(111.51,27.81) v1(111.76,66.29) v1(111.89,86.23) v1(111.89,22.35) v1(112.01,83.19) v1(112.01,80.39) v1(112.01,42.8) v1(112.01,40.77) v1(112.01,19.43) v1(112.14,24.77) v1(112.14,8) v1(112.27,63.12) v1(112.27,60.2) v1(112.27,57.91) v1(112.39,55.18) v1(112.39,16.57) v1(112.39,0.95) v1(112.52,87.5) v1(112.52,84.96) v1(112.52,76.01) v1(112.52,46.1) v1(112.52,37.66) v1(112.65,81.91) v1(112.65,79.12) v1(112.65,27.81) v1(112.9,66.29) v1(112.9,43.81) v1(112.9,41.66) v1(112.9,39.37) v1(112.9,23.5) v1(112.9,21.21) v1(113.03,103.31) v1(113.16,86.23) v1(113.16,61.21) v1(113.16,59.05) v1(113.28,83.19) v1(113.28,80.39) v1(113.29,25.78) v1(113.28,24.64) v1(113.28,19.43) v1(113.41,63.12) v1(113.41,57.91) v1(113.41,56.52) v1(113.41,8) v1(113.67,64.26) v1(113.67,46.1) v1(113.79,87.5) v1(113.79,84.96) v1(113.79,28.07) v1(113.79,22.48) v1(113.92,81.91) v1(113.92,79.12) v1(113.92,66.8) v1(113.92,42.8) v1(113.92,40.64) v1(113.98,53.53) v1(113.98,16.57) v1(113.98,14.92) v1(113.98,0.95) v1(114.11,76.01) v1(114.11,74.49) v1(114.11,37.66) v1(114.11,36) v1(114.17,60.2) v1(114.17,55.75) v1(114.17,26.67) v1(114.3,57.4) v1(114.3,54.74) v1(114.3,25.53) v1(114.3,19.18) v1(114.43,86.23) v1(114.43,67.82) v1(114.43,28.96) v1(114.55,83.19) v1(114.55,80.39) v1(114.55,65.53) v1(114.55,63.25) v1(114.62,103.31) v1(114.68,43.81) v1(114.68,41.66) v1(114.68,39.37) v1(114.68,23.37) v1(114.68,21.08) v1(114.68,8) v1(114.81,64.39) v1(114.81,46.1) v1(114.94,61.21) v1(114.94,59.05) v1(114.94,27.43) v1(115.06,87.5) v1(115.06,84.96) v1(115.06,56.64) v1(115.06,18.29) v1(115.19,81.91) v1(115.19,79.12) v1(115.32,66.29) v1(115.44,62.23) v1(115.57,65.15) v1(115.57,57.91) v1(115.57,55.75) v1(115.57,0.95) v1(115.7,86.23) v1(115.7,67.31) v1(115.7,54.74) v1(115.7,37.66) v1(115.7,29.21) v1(115.7,28.19) v1(115.7,24.51) v1(115.7,22.35) v1(115.7,17.4) v1(115.7,16.26) v1(115.7,15.11) v1(115.7,13.97) v1(115.82,83.19) v1(115.82,80.39) v1(115.82,42.8) v1(115.82,40.64) v1(115.95,46.1) v1(115.95,8) v1(116.08,60.2) v1(116.2,103.31) v1(116.33,87.5) v1(116.33,84.96) v1(116.33,66.04) v1(116.46,81.91) v1(116.46,79.12) v1(116.46,61.21) v1(116.46,23.37) v1(116.46,21.08) v1(116.59,67.44) v1(116.59,56.9) v1(116.97,86.23) v1(117.09,83.19) v1(117.09,80.39) v1(117.09,46.1) v1(117.16,0.95) v1(117.22,62.23) v1(117.35,57.91) v1(117.28,37.66) v1(117.6,87.5) v1(117.6,84.96) v1(117.73,81.91) v1(117.73,79.12) v1(117.79,103.31) v1(118.43,101.73) v1(118.43,100.14) v1(118.43,98.55) v1(118.43,96.96) v1(118.43,95.38) v1(118.43,93.79) v1(118.43,92.2) v1(118.43,90.61) v1(118.43,89.03) v1(118.43,87.44) v1(118.43,85.85) v1(118.43,84.26) v1(118.43,82.68) v1(118.43,81.09) v1(118.43,79.5) v1(118.43,77.91) v1(118.43,76.33) v1(118.43,72.83) v1(118.43,71.25) v1(118.43,66.8) v1(118.43,65.21) v1(118.43,63.63) v1(118.43,62.04) v1(118.43,60.45) v1(118.43,58.86) v1(118.43,57.28) v1(118.43,55.69) v1(118.43,50.93) v1(118.43,46.16) v1(118.43,44.58) v1(118.43,42.99) v1(118.43,41.4) v1(118.43,39.81) v1(118.43,38.23) v1(118.43,33.46) v1(118.43,28.7) v1(118.43,27.11) v1(118.43,25.53) v1(118.43,23.94) v1(118.43,22.35) v1(118.43,20.76) v1(118.43,19.18) v1(118.43,17.59) v1(118.43,12.83) v1(118.43,11.24) v1(118.43,8.06) v1(118.43,6.48) v1(118.43,4.89) v1(118.43,3.3) v1(118.43,1.71)
